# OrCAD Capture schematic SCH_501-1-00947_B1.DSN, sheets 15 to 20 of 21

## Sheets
15 P12_WiFI/BT: size A2
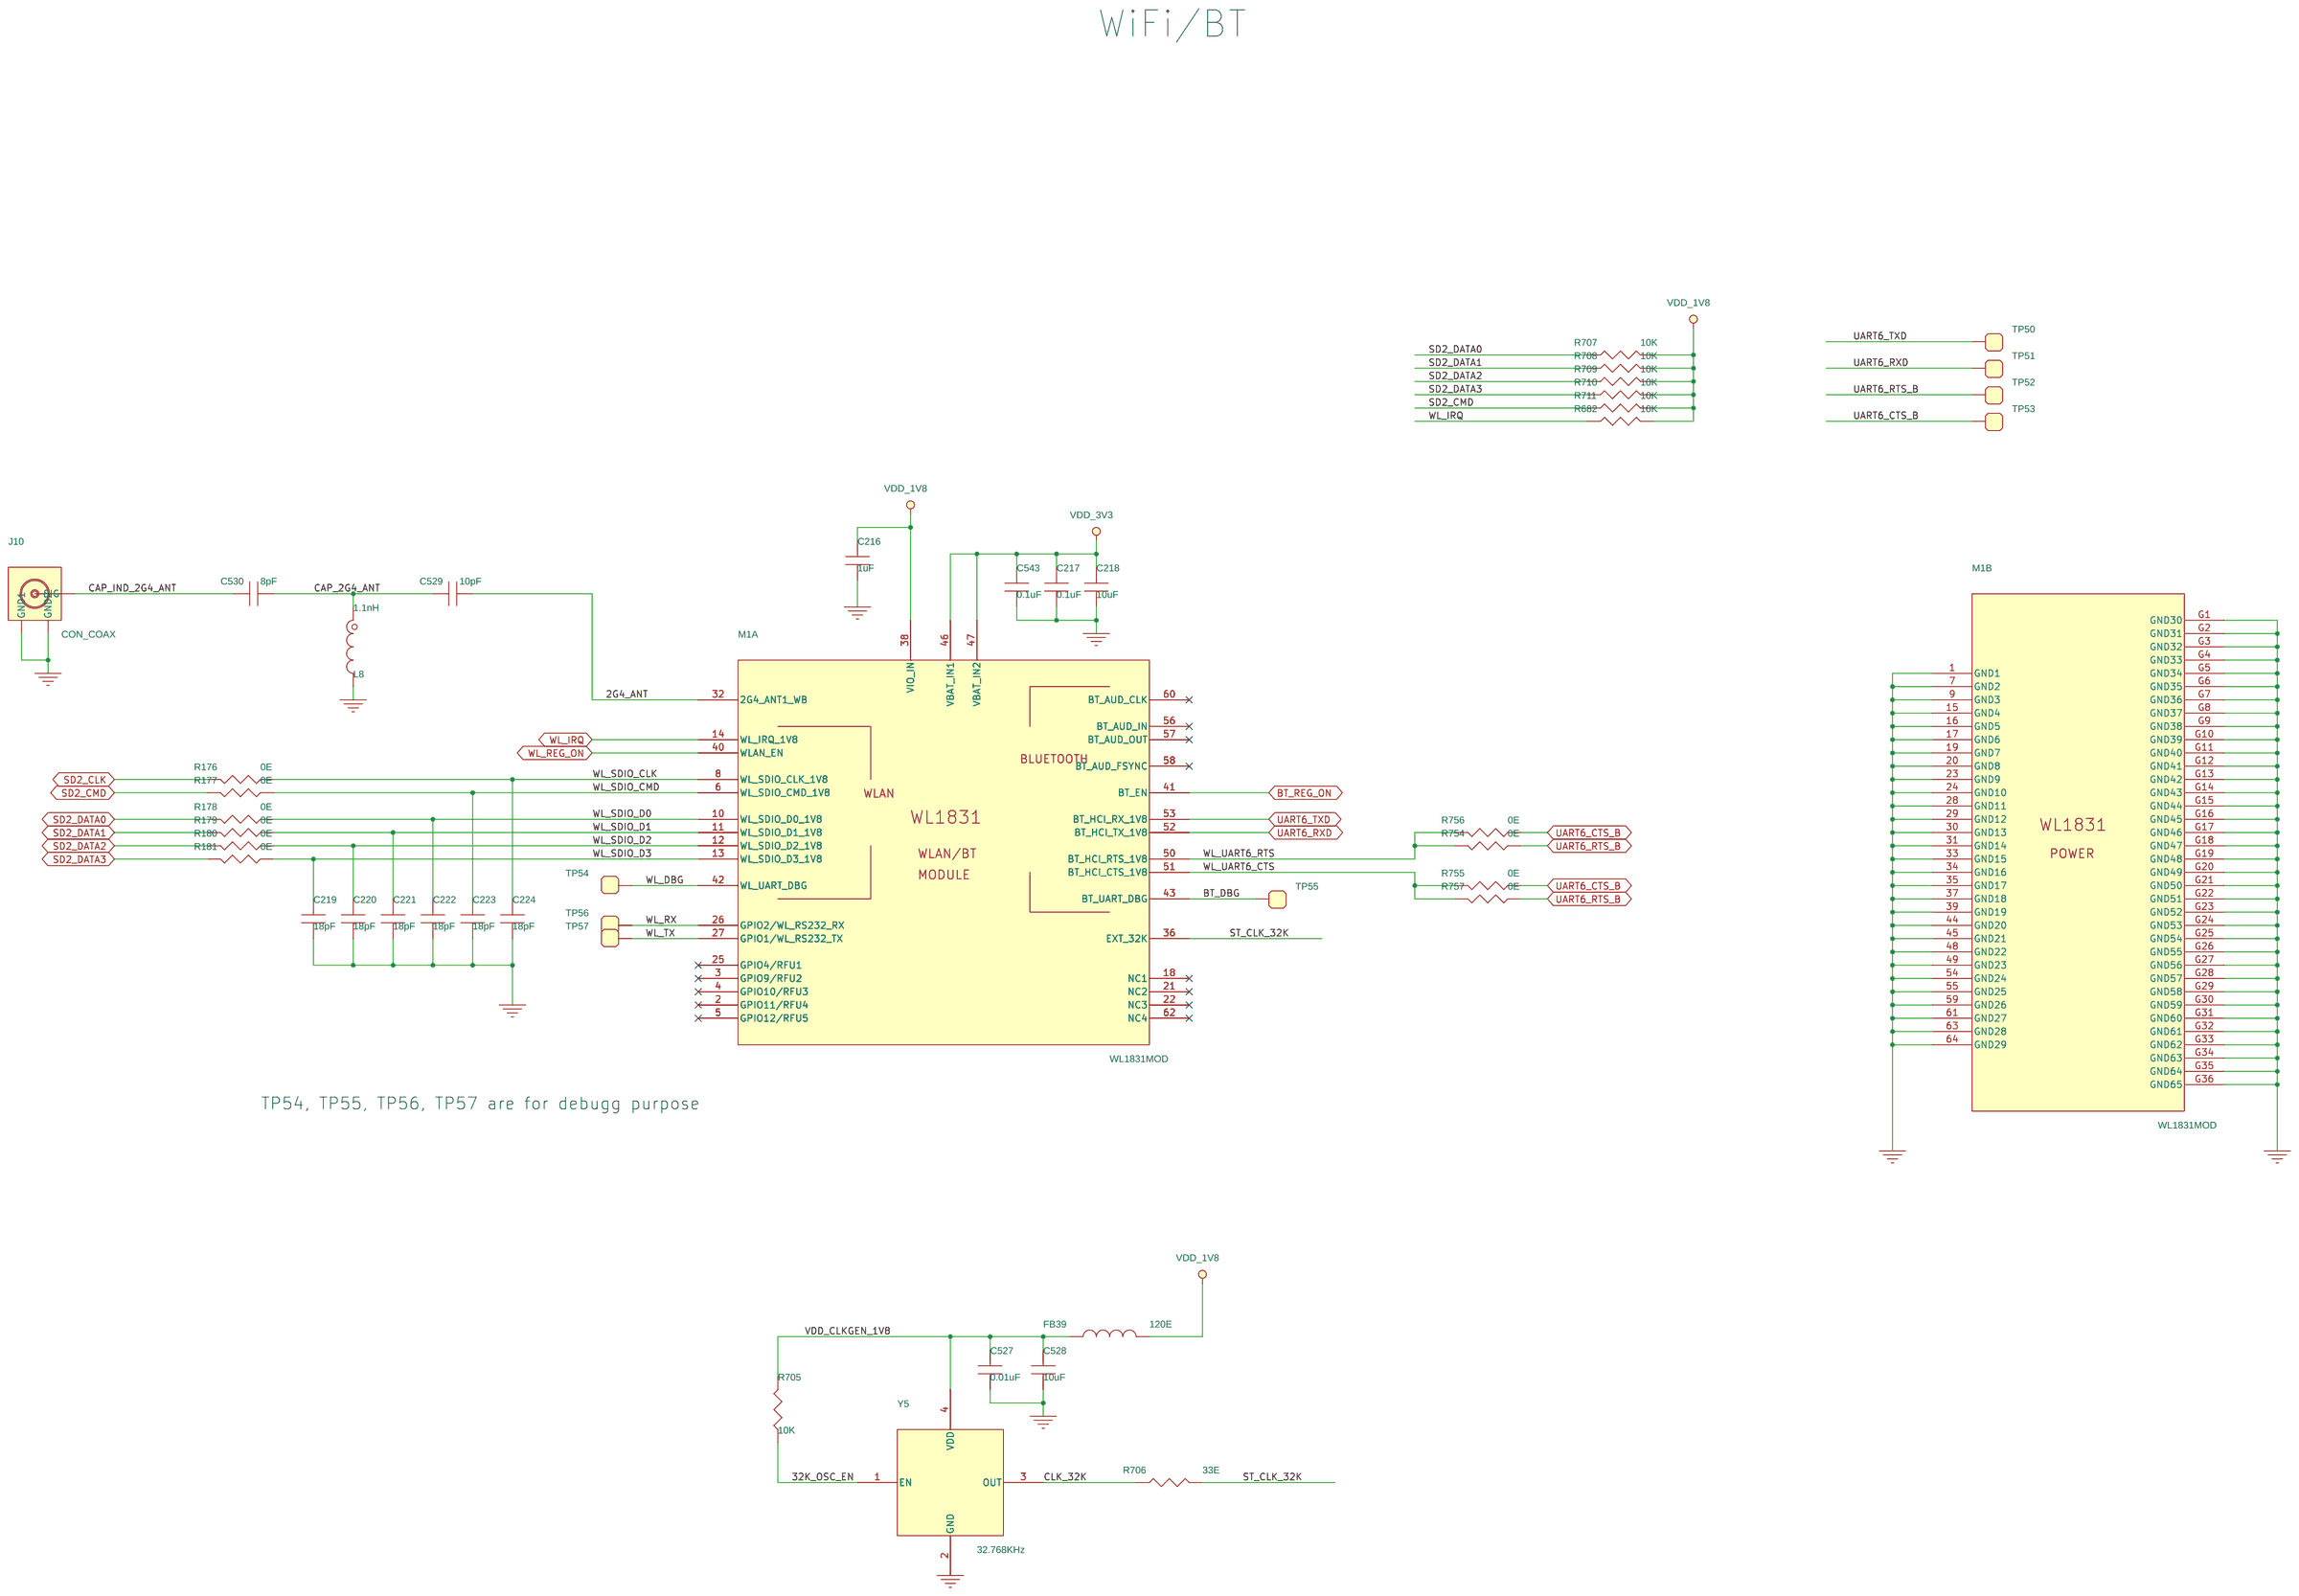
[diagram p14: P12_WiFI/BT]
16 P18_USB/BUTTON: size A2
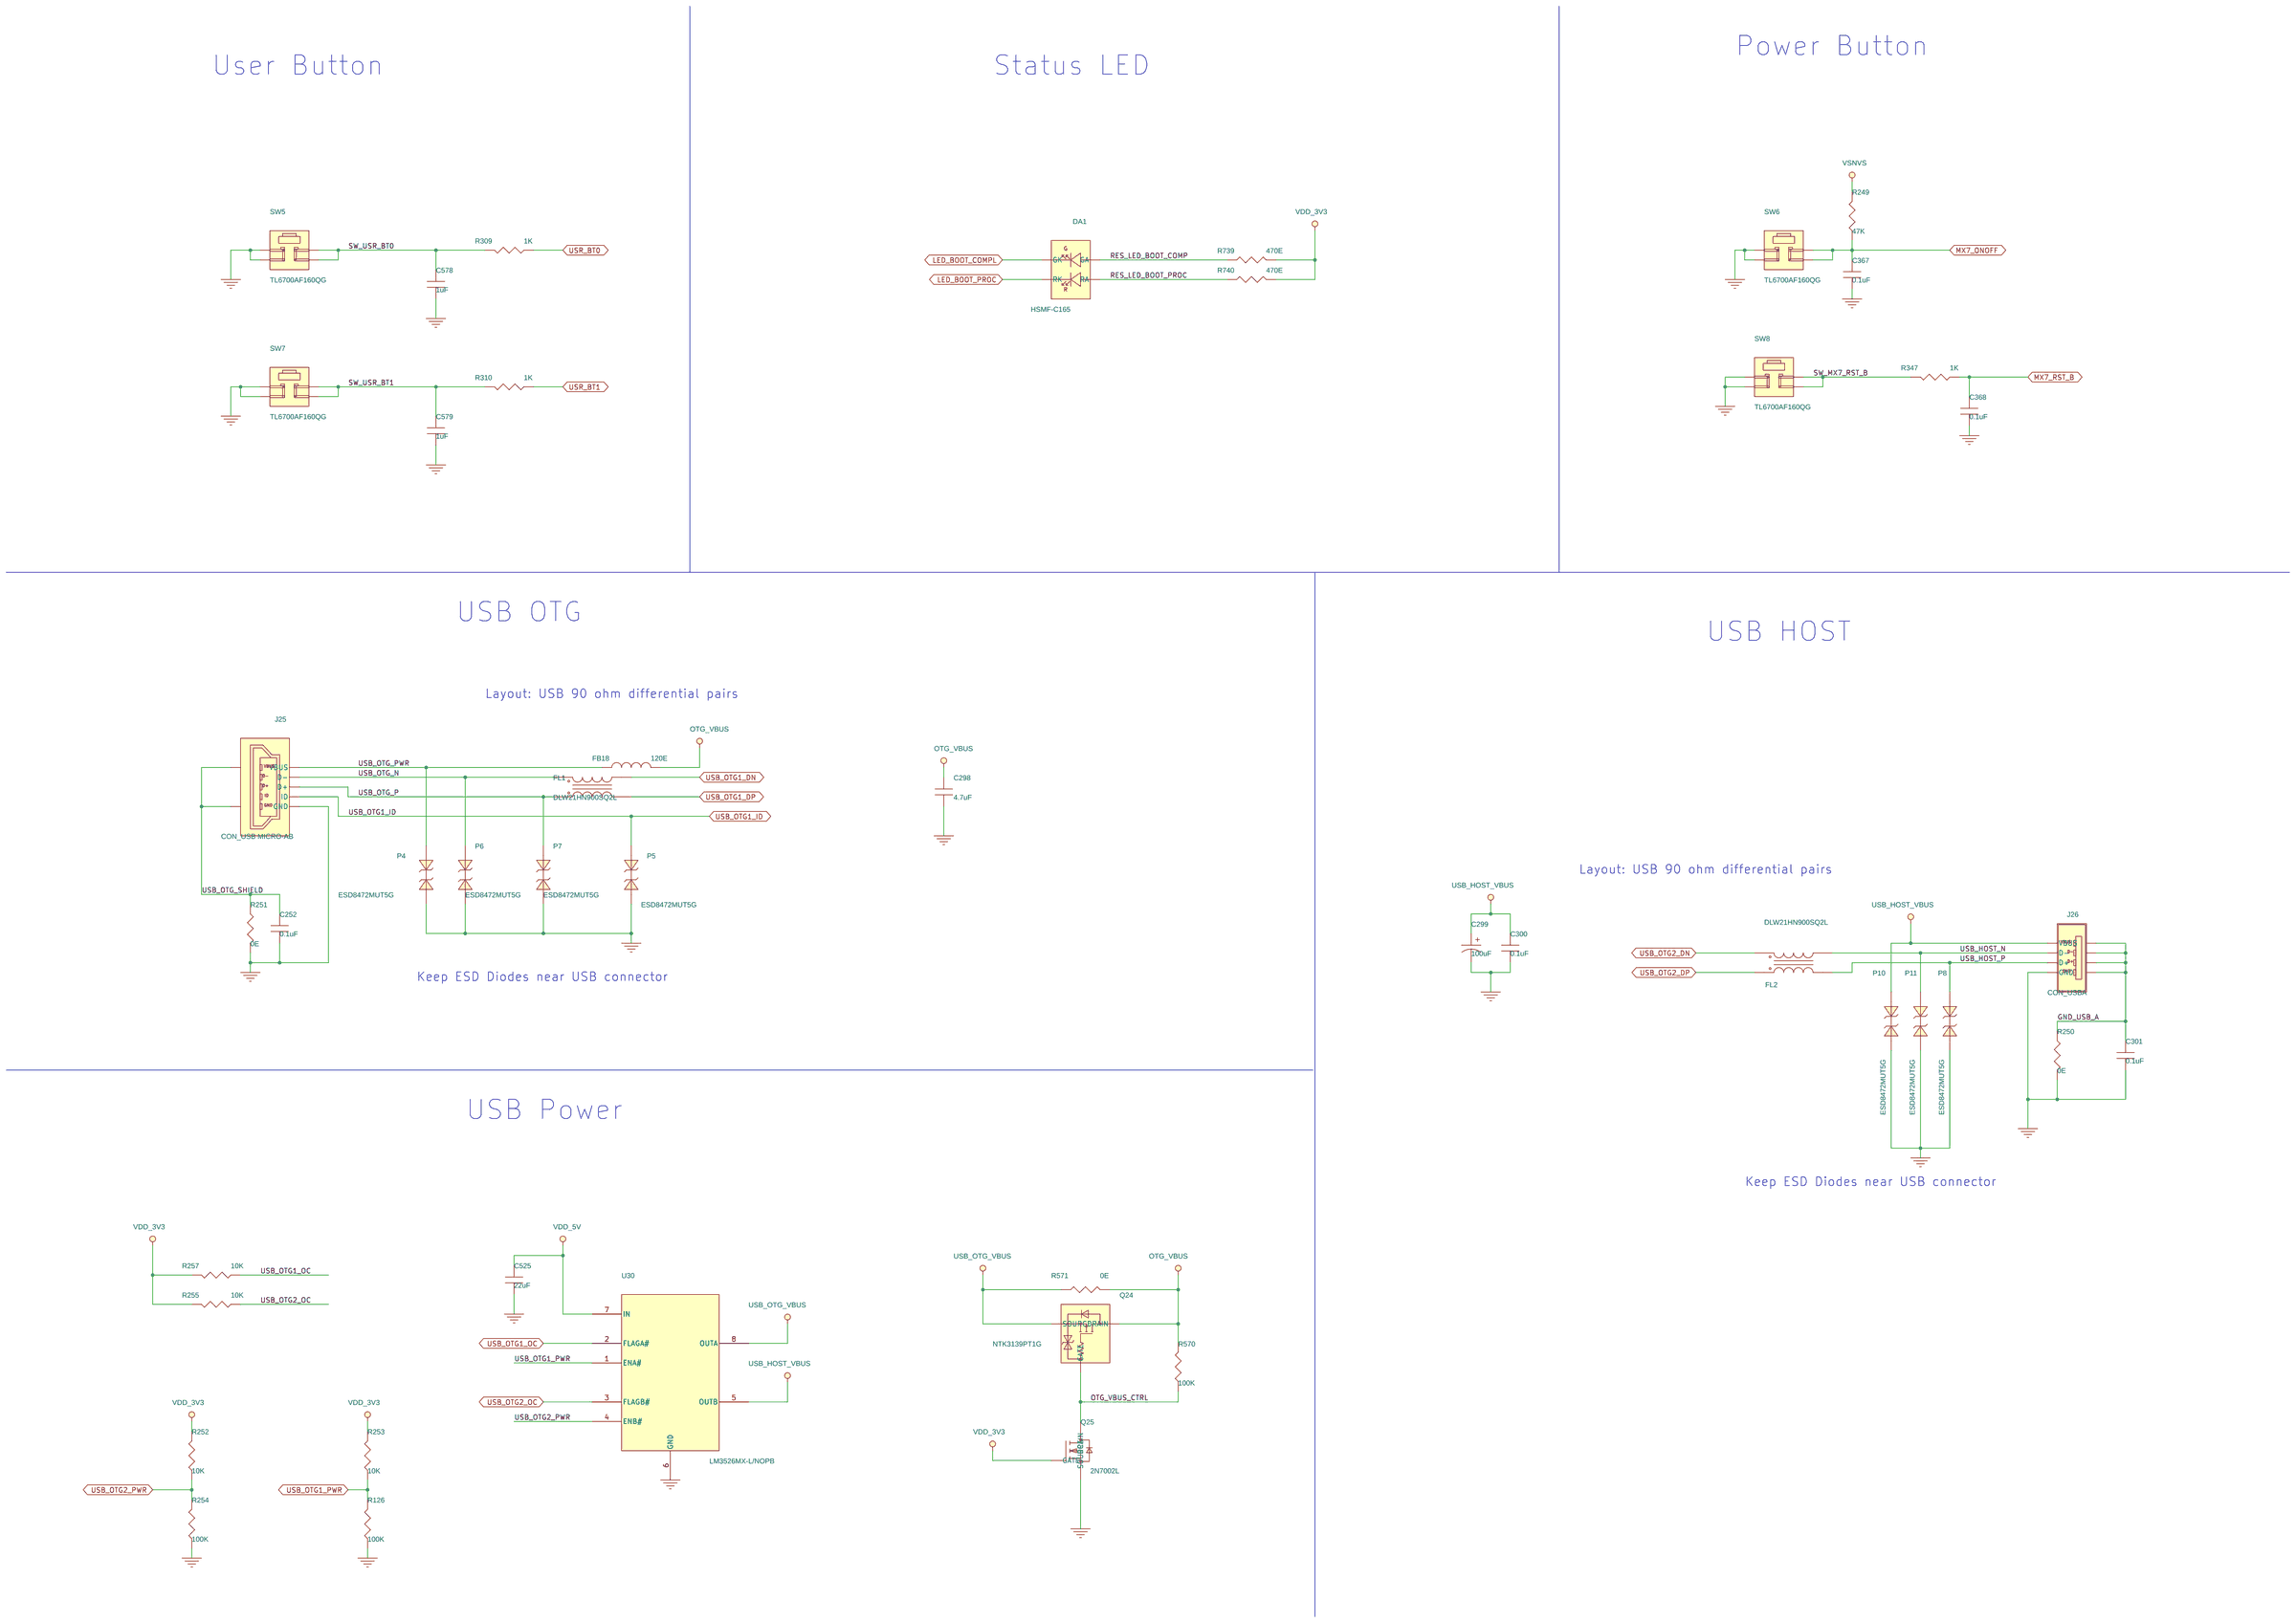
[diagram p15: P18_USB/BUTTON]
17 P16_CAN/LCD/ALS: size A2
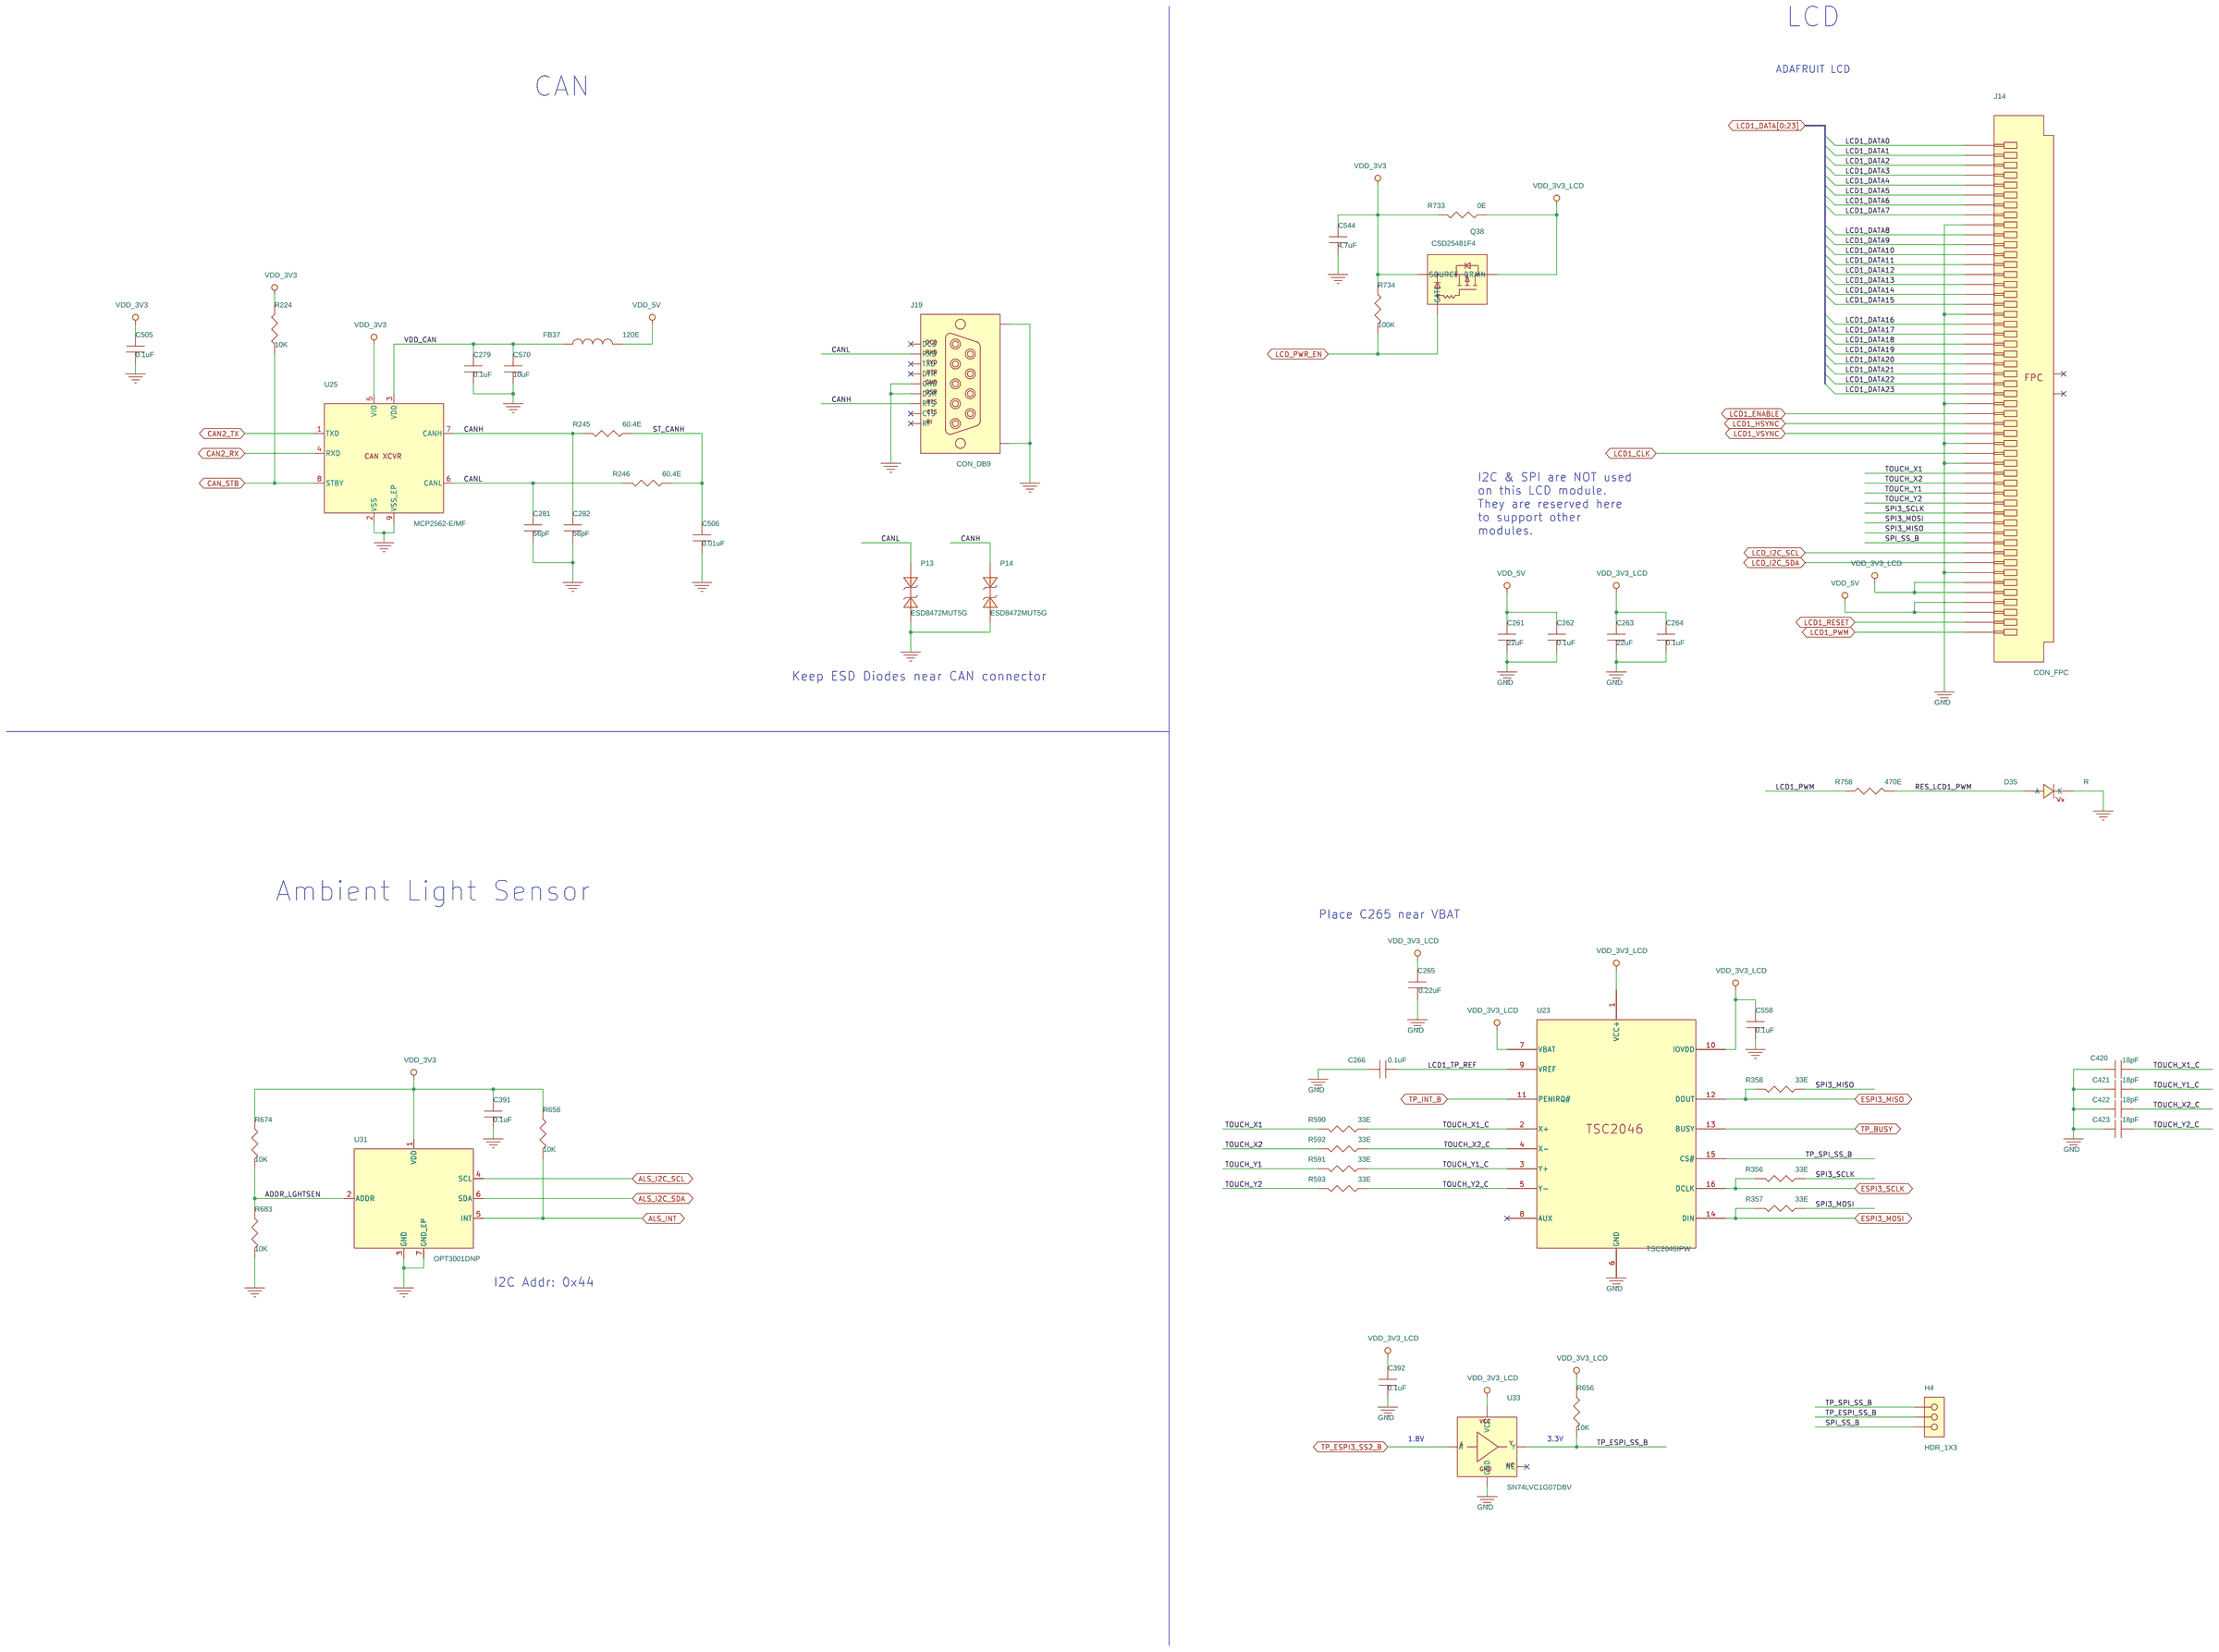
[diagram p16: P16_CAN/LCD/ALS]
18 P10_eMMC/FLASH/SD: size A2
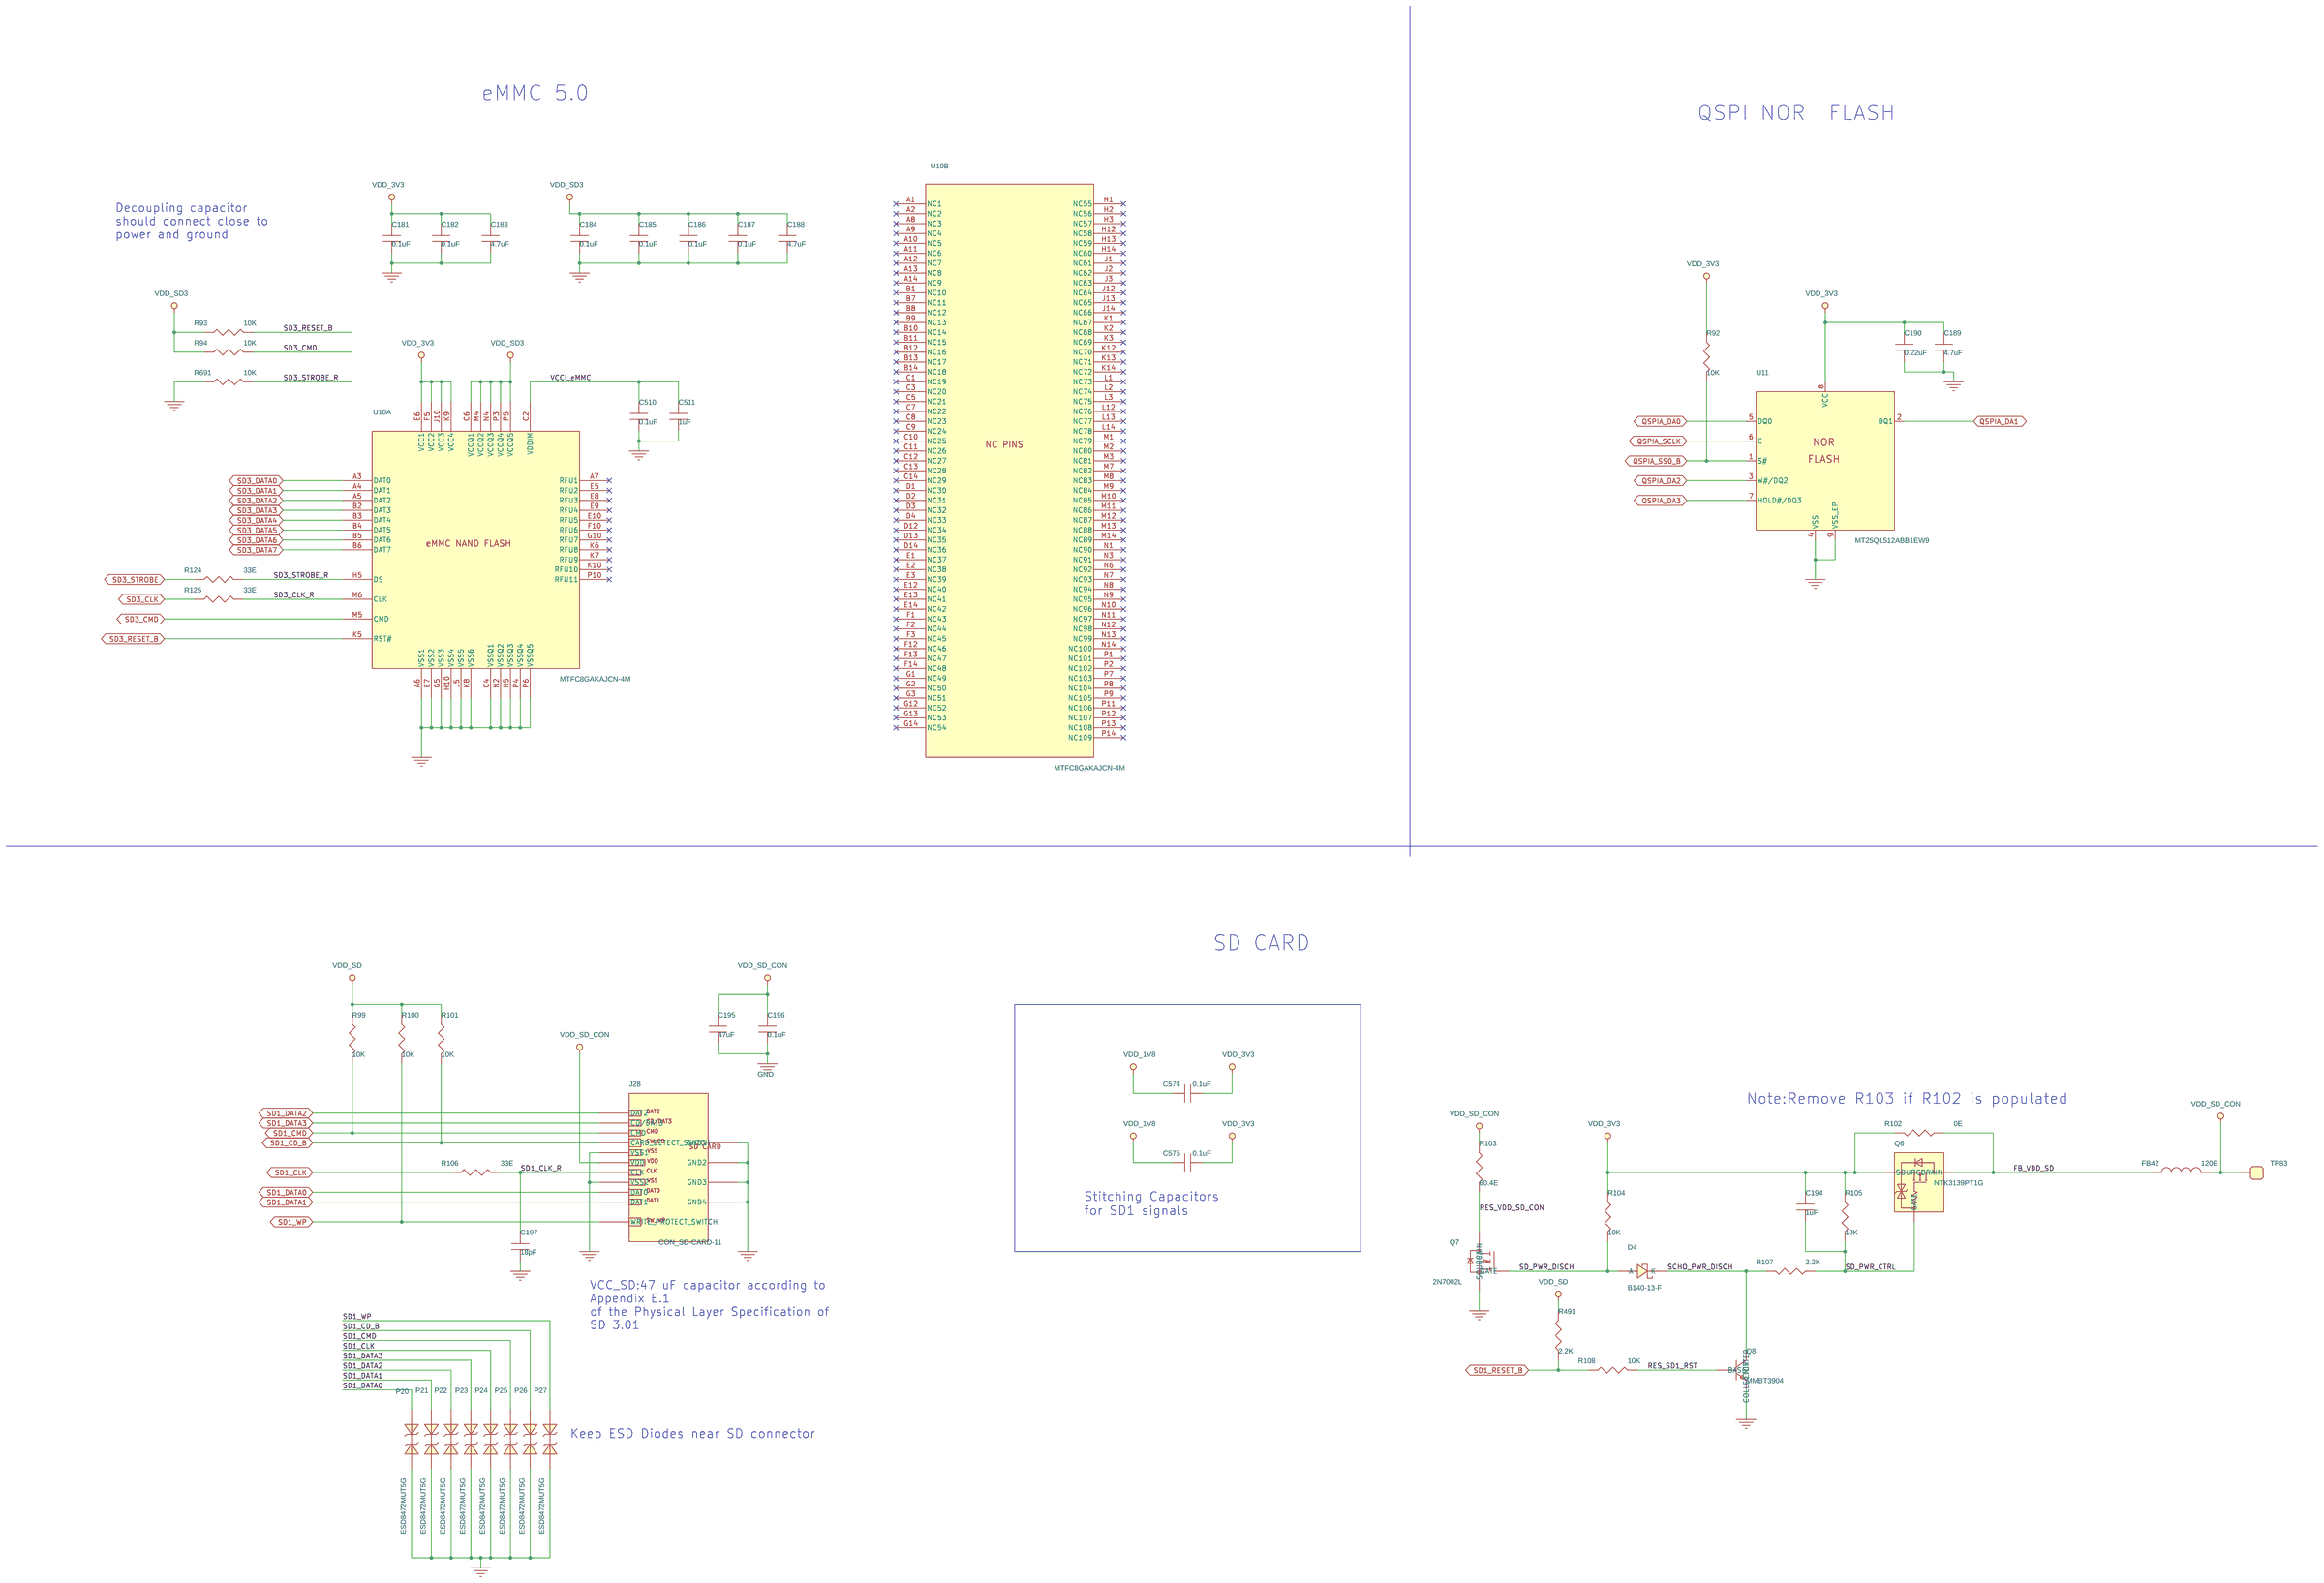
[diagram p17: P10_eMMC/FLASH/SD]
19 P20_CSI/WATCHDOG/IO: size A2
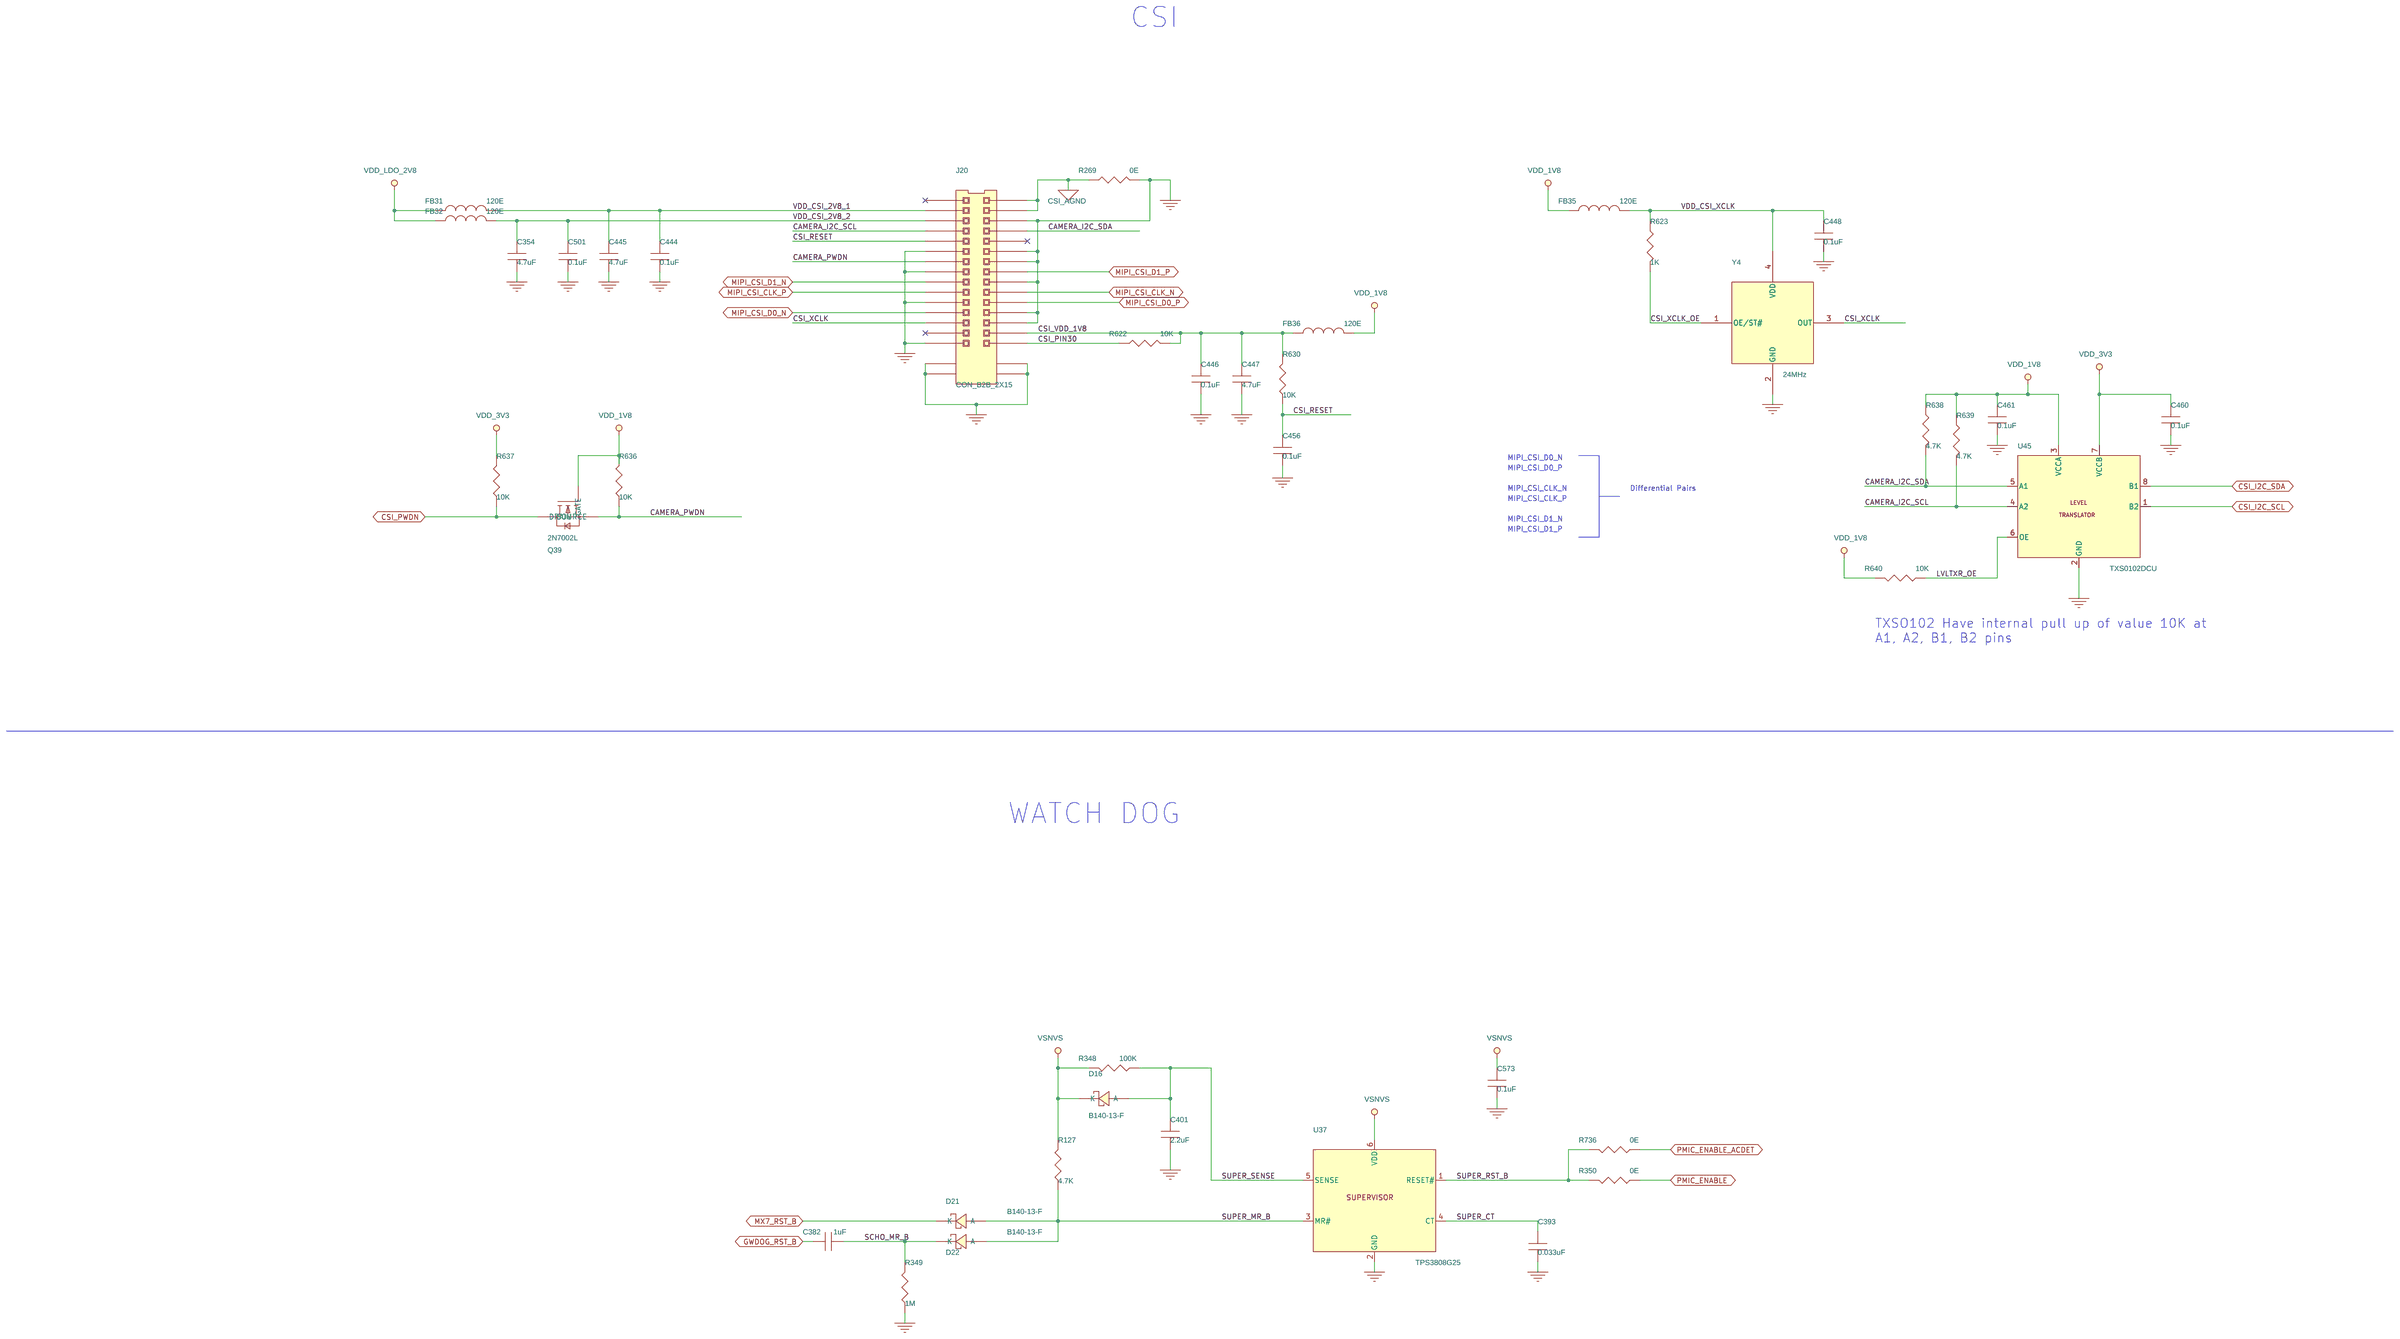
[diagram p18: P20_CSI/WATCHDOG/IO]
20 P13_DEBUG UART/JTAG: size A2
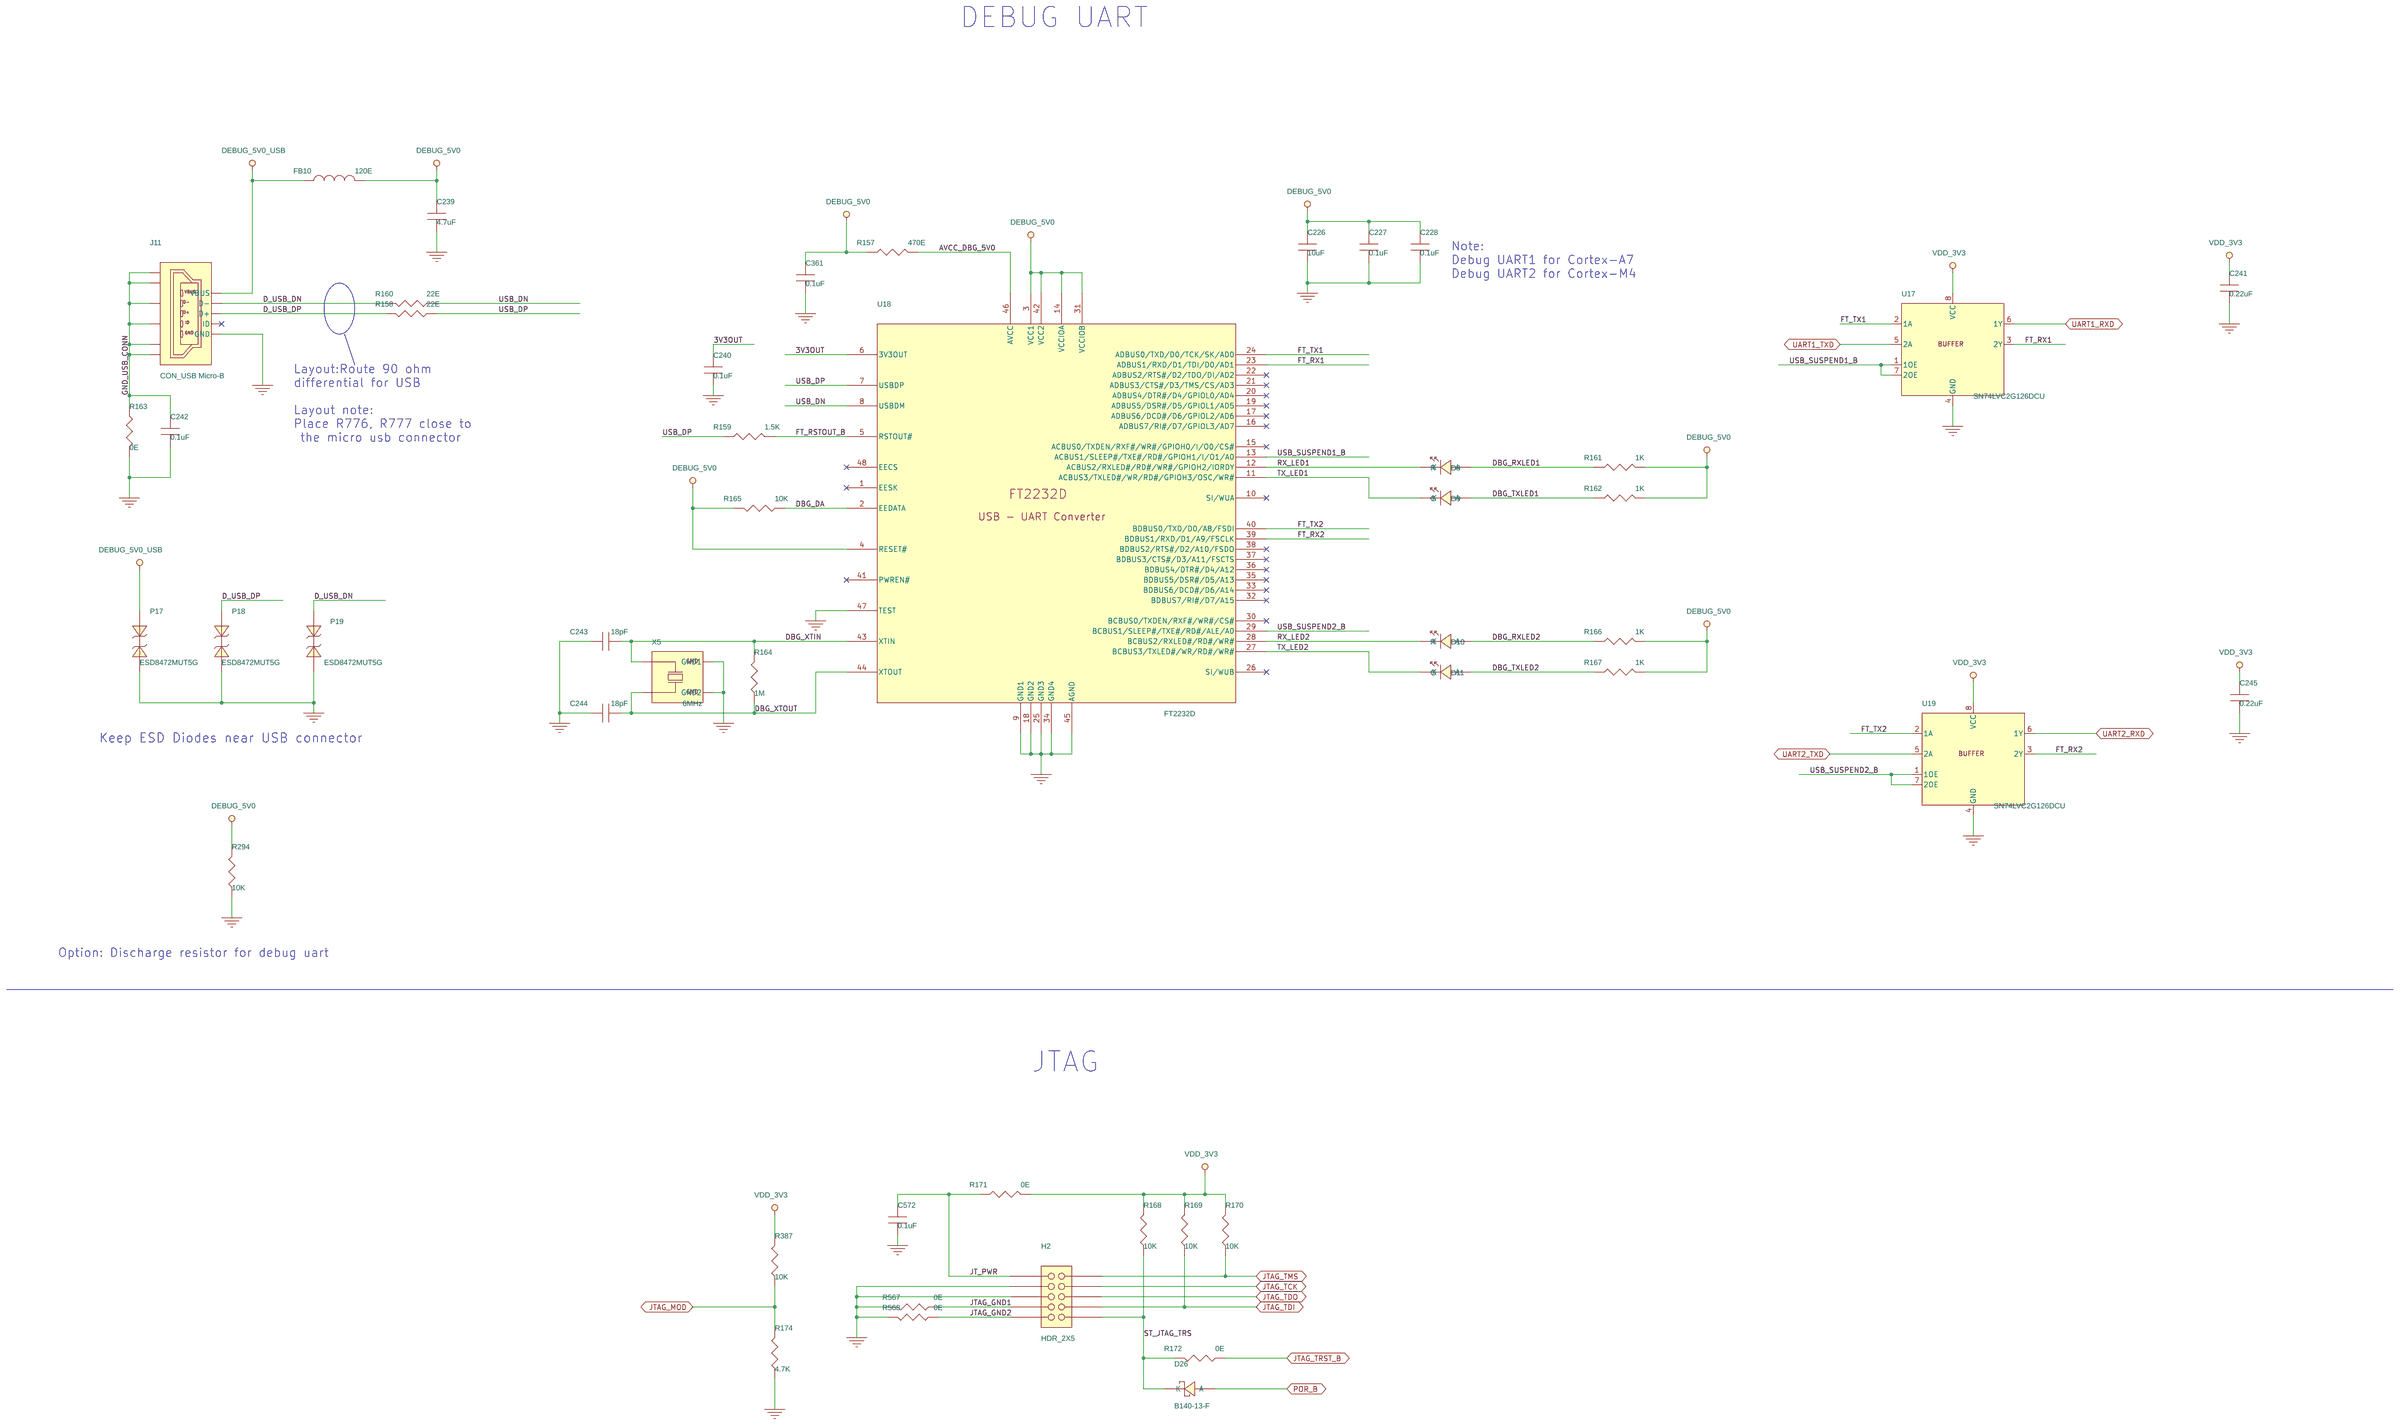
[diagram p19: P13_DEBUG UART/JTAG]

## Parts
sheet P10_eMMC/FLASH/SD
C181  0.1uF  [C0402]
C182  0.1uF  [C0402]
C183  4.7uF  [C0603]
C184  0.1uF  [C0402]
C185  0.1uF  [C0402]
C186  0.1uF  [C0402]
C187  0.1uF  [C0402]
C188  4.7uF  [C0603]
C189  4.7uF  [C0603]
C190  0.22uF  [C0402]
C194  1uF  [C0603]
C195  47uF  [0805_B_A1]
C196  0.1uF  [C0402]
C197  18pF  [C0402]
C510  0.1uF  [C0402]
C511  1uF  [C0603]
C574  0.1uF  [C0402]
C575  0.1uF  [C0402]
D4  B140-13-F  [DIO_SMA]
FB42  120E  [0402]
J28  CON_SD-CARD-11  [CON_SDCARD_11F_2P5_SM_RA_A_A1]
P20  ESD8472MUT5G  [DIO-0201]
P21  ESD8472MUT5G  [DIO-0201]
P22  ESD8472MUT5G  [DIO-0201]
P23  ESD8472MUT5G  [DIO-0201]
P24  ESD8472MUT5G  [DIO-0201]
P25  ESD8472MUT5G  [DIO-0201]
P26  ESD8472MUT5G  [DIO-0201]
P27  ESD8472MUT5G  [DIO-0201]
Q6  NTK3139PT1G  [SOT723-3L_0P4_1P2X0P8]
Q7  2N7002L  [sot23_123]
Q8  MMBT3904  [sot23_123]
R92  10K  [R0402]
R93  10K  [R0402]
R94  10K  [R0402]
R99  10K  [R0402]
R100  10K  [R0402]
R101  10K  [R0402]
R102  0E  [R0402]
R103  60.4E  [R0805]
R104  10K  [R0402]
R105  10K  [R0402]
R106  33E  [R0402]
R107  2.2K  [R0402]
R108  10K  [R0402]
R124  33E  [R0402]
R125  33E  [R0402]
R491  2.2K  [R0402]
R691  10K  [R0402]
TP83  SMD  [TP40_SMD]
U10  MTFC8GAKAJCN-4M  [BGA153_0P5_11P5X13_C_A1]  (sections A,B)
U11  MT25QL512ABB1EW9  [DFN8_1P27_8X6_EP_A_A1]
sheet P12_WiFI/BT
C216  1uF  [C0603]
C217  0.1uF  [C0402]
C218  10uF  [C0603]
C219  18pF  [C0402]
C220  18pF  [C0402]
C221  18pF  [C0402]
C222  18pF  [C0402]
C223  18pF  [C0402]
C224  18pF  [C0402]
C527  0.01uF  [C0402]
C528  10uF  [C0603]
C529  10pF  [0402]
C530  8pF  [0402]
C543  0.1uF  [C0402]
FB39  120E  [0402]
J10  CON_COAX  [CON_COAXIAL_3F_1P475_SM_ST]
L8  1.1nH  [IND_0402-POL]
M1  WL1831MOD  [MOD-WIFI-BT64_0P7_13P4X13P3]  (sections A,B)
R176  0E  [R0402]
R177  0E  [R0402]
R178  0E  [R0402]
R179  0E  [R0402]
R180  0E  [R0402]
R181  0E  [R0402]
R682  10K  [R0402]
R705  10K  [R0402]
R706  33E  [R0402]
R707  10K  [R0402]
R708  10K  [R0402]
R709  10K  [R0402]
R710  10K  [R0402]
R711  10K  [R0402]
R754  0E  [R0402]
R755  0E  [R0402]
R756  0E  [R0402]
R757  0E  [R0402]
TP50  SMD  [TP40_SMD]
TP51  SMD  [TP40_SMD]
TP52  SMD  [TP40_SMD]
TP53  SMD  [TP40_SMD]
TP54  SMD  [TP40_SMD]
TP55  SMD  [TP40_SMD]
TP56  SMD  [TP40_SMD]
TP57  SMD  [TP40_SMD]
Y5  32.768KHz  [OSC4_3P2X2P5_SMD]
sheet P13_DEBUG UART/JTAG
C226  10uF  [C0603]
C227  0.1uF  [C0402]
C228  0.1uF  [C0402]
C239  4.7uF  [C0603]
C240  0.1uF  [C0402]
C241  0.22uF  [C0402]
C242  0.1uF  [C0402]
C243  18pF  [C0402]
C244  18pF  [C0402]
C245  0.22uF  [C0402]
C361  0.1uF  [C0402]
C572  0.1uF  [C0402]
D8  R  [LED2_1P5_1P6X0P8_A_A1]
D9  G  [LED2_1P5_1P6X0P8_A_A1]
D10  R  [LED2_1P5_1P6X0P8_A_A1]
D11  G  [LED2_1P5_1P6X0P8_A_A1]
D26  B140-13-F  [DIO_SMA]
FB10  120E  [0402]
H2  HDR_2X5  [CON_B2B_2X5M_1P27_SM_ST]
J11  CON_USB Micro-B  [CON_USB_1X1-5F_0P65_SM_RA_D_A1]
P17  ESD8472MUT5G  [DIO-0201]
P18  ESD8472MUT5G  [DIO-0201]
P19  ESD8472MUT5G  [DIO-0201]
R157  470E  [R0402]
R158  22E  [R0402]
R159  1.5K  [R0402]
R160  22E  [R0402]
R161  1K  [R0402]
R162  1K  [R0402]
R163  0E  [R0402]
R164  1M  [R0402]
R165  10K  [R0402]
R166  1K  [R0402]
R167  1K  [R0402]
R168  10K  [R0402]
R169  10K  [R0402]
R170  10K  [R0402]
R171  0E  [R0402]
R172  0E  [R0402]
R174  4.7K  [R0402]
R294  10K  [R0402]
R387  10K  [R0402]
R567  0E  [R0402]
R568  0E  [R0402]
U17  SN74LVC2G126DCU  [dcu8p5r]
U18  FT2232D  [QFP48p5j]
U19  SN74LVC2G126DCU  [dcu8p5r]
X5  6MHz  [XTAL4_2P54_7X5_A_A1]
sheet P16_CAN/LCD/ALS
C261  22uF  [C0603]
C262  0.1uF  [C0402]
C263  22uF  [C0603]
C264  0.1uF  [C0402]
C265  0.22uF  [C0402]
C266  0.1uF  [C0402]
C279  0.1uF  [C0402]
C281  56pF  [C0402]
C282  56pF  [C0402]
C391  0.1uF  [C0402]
C392  0.1uF  [C0402]
C420  18pF  [C0402]
C421  18pF  [C0402]
C422  18pF  [C0402]
C423  18pF  [C0402]
C505  0.1uF  [C0402]
C506  0.01uF  [C0402]
C544  4.7uF  [C0603]
C558  0.1uF  [C0402]
C570  10uF  [C0603]
D35  R  [LED2_1P5_1P6X0P8_A_A1]
FB37  120E  [0402]
H4  HDR_1X3  [CON_BERG_3M_2P54_TH_54101]
J14  CON_FPC  [CON_FPC_50F_0P5_SM_RA]
J19  CON_DB9  [CON_DB_9M_2P74_5747840-4]
P13  ESD8472MUT5G  [DIO-0201]
P14  ESD8472MUT5G  [DIO-0201]
Q38  CSD25481F4  [MOSFET_0402-3L_A1]
R224  10K  [R0402]
R245  60.4E  [R0805]
R246  60.4E  [R0805]
R356  33E  [R0402]
R357  33E  [R0402]
R358  33E  [R0402]
R590  33E  [R0402]
R591  33E  [R0402]
R592  33E  [R0402]
R593  33E  [R0402]
R656  10K  [R0402]
R658  10K  [R0402]
R674  10K  [R0402]
R683  10K  [R0402]
R733  0E  [R0402]
R734  100K  [R0402]
R758  470E  [R0402]
U23  TSC2046IPW  [tssop16fa]
U25  MCP2562-E/MF  [DFN8_0P65_3X3_EP_A]
U31  OPT3001DNP  [SON6_0P65_2X2_EP_A_A1]
U33  SN74LVC1G07DBV  [SOT23-5L_0P95_3P05X1P75]
sheet P18_USB/BUTTON
C252  0.1uF  [C0402]
C298  4.7uF  [C0603]
C299  100uF  [TCAP_CASEB]
C300  0.1uF  [C0402]
C301  0.1uF  [C0402]
C367  0.1uF  [C0402]
C368  0.1uF  [C0402]
C525  22uF  [C0603]
C578  1uF  [0402]
C579  1uF  [0402]
DA1  HSMF-C165  [LED4_0P7_1P6X0P8]
FB18  120E  [0402]
FL1  DLW21HN900SQ2L  [CM_CHK4_0P8_2X1P2]
FL2  DLW21HN900SQ2L  [CM_CHK4_0P8_2X1P2]
J25  CON_USB MICRO-AB  [CON_USB_5F_0P65_SM_RA]
J26  CON_USBA  [CON_USB-A_1X1F_2_TH_RA_D_A1]
P4  ESD8472MUT5G  [DIO-0201]
P5  ESD8472MUT5G  [DIO-0201]
P6  ESD8472MUT5G  [DIO-0201]
P7  ESD8472MUT5G  [DIO-0201]
P8  ESD8472MUT5G  [DIO-0201]
P10  ESD8472MUT5G  [DIO-0201]
P11  ESD8472MUT5G  [DIO-0201]
Q24  NTK3139PT1G  [SOT723-3L_0P4_1P2X0P8]
Q25  2N7002L  [sot23_123]
R126  100K  [R0402]
R249  47K  [R0402]
R250  0E  [R0402]
R251  0E  [R0402]
R252  10K  [R0402]
R253  10K  [R0402]
R254  100K  [R0402]
R255  10K  [R0402]
R257  10K  [R0402]
R309  1K  [R0402]
R310  1K  [R0402]
R347  1K  [R0402]
R570  100K  [R0402]
R571  0E  [R0402]
R739  470E  [R0402]
R740  470E  [R0402]
SW5  TL6700AF160QG  [SW4_4_6P9X6P2]
SW6  TL6700AF160QG  [SW4_4_6P9X6P2]
SW7  TL6700AF160QG  [SW4_4_6P9X6P2]
SW8  TL6700AF160QG  [SW4_4_6P9X6P2]
U30  LM3526MX-L/NOPB  [SOIC8_1P27_4X5]
sheet P20_CSI/WATCHDOG/IO
C354  4.7uF  [C0603]
C382  1uF  [C0603]
C393  0.033uF  [C0402]
C401  2.2uF  [C0402]
C444  0.1uF  [C0402]
C445  4.7uF  [C0603]
C446  0.1uF  [C0402]
C447  4.7uF  [C0603]
C448  0.1uF  [C0402]
C456  0.1uF  [C0402]
C460  0.1uF  [C0402]
C461  0.1uF  [C0402]
C501  0.1uF  [C0402]
C573  0.1uF  [C0402]
D16  B140-13-F  [DIO_SMA]
D21  B140-13-F  [DIO_SMA]
D22  B140-13-F  [DIO_SMA]
FB31  120E  [0402]
FB32  120E  [0402]
FB35  120E  [0402]
FB36  120E  [0402]
J20  CON_B2B_2X15  [fpc2x15_4p4_a]
Q39  2N7002L  [sot23_123]
R127  4.7K  [R0402]
R269  0E  [R0402]
R348  100K  [R0402]
R349  1M  [R0402]
R350  0E  [R0402]
R622  10K  [R0402]
R623  1K  [R0402]
R630  10K  [R0402]
R636  10K  [R0402]
R637  10K  [R0402]
R638  4.7K  [R0402]
R639  4.7K  [R0402]
R640  10K  [R0402]
R736  0E  [R0402]
U37  TPS3808G25  [SOT23-6L_0P95_3P05X1P75]
U45  TXS0102DCU  [ssop8cr]
Y4  24MHz  [OSC4_1P9_3P2X2P5_C_A1]

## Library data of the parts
C181 C182 C184-C187 C196 C217 C227 C228 C240 C279 C391 C392 C505 C510 C543 C558 C572-C575 = CAP_NP: Cap, Cer-X7R, 0.1uF, 16V, 10%, 0402; EN: 102-1-01629; KEY Number: 102-1-01629@4; Mfg: MURATA MANUFACTURING CO,LTD; Mfg Part No: GRM155R71C104KA88*; Temperature: -55°C to +125°C
C183 C188 C189 C354 C445 C447 = CAP_NP: Cap, Cer-X5R, 4.7uF, 10V, 10%, 0603; EN: 102-1-01650; KEY Number: 102-1-01650@2; Mfg: WALSIN TECHNOLOGY CORP.; Mfg Part No: 0603X475K100CT; Temperature: -55°C to +85°C
C190 C241 C245 C265 = CAP_NP: Cap, Cer-X5R, 0.22uF, 10V, 10%, 0402; EN: 102-1-00210; FPLIST: 0402,0402_CIR_A1; KEY Number: 102-1-00210@1; Mfg: MURATA MANUFACTURING CO,LTD; Mfg Part No: GRM155R61A224KE19D; Temperature: -55°C to +85°C
C194 C216 C382 C511 = CAP_NP: Cap, Cer-X7R, 1uF, 10V, 10%, 0603; EN: 102-1-00097; FPLIST: 0603,0603_HD; KEY Number: 102-1-00097@1; Mfg: AVX CORPORATION; Mfg Part No: 0603ZC105KAT2A; Temperature: -55°C to +125°C
C195 = CAP_NP: Cap, Cer-X5R, 47uF, 10V, 20%, 0805; EN: 102-1-02136; KEY Number: 102-1-02136@1; Mfg: MURATA MANUFACTURING CO,LTD; Mfg Part No: GRM21BR61A476ME15L; Temperature: -55°C to +85°C
C197 C219-C224 C243 C244 C420-C423 = CAP_NP: Cap, Cer-NPO, 18pF, 50V, 5%, 0402; EN: 102-1-01806; KEY Number: 102-1-01806@1; Mfg: MURATA MANUFACTURING CO,LTD; Mfg Part No: GRM1555C1H180JA01D; Temperature: -55°C to +125°C
D4 D16 D21 D22 D26 = DIODE_SCH: Diode, Schottky, 1A, 40V, SMA; EN: 106-2-00036; KEY Number: 106-2-00036@1; Mfg: DIODES INCORPORATED
FB10 FB18 FB31 FB32 FB35-FB37 FB39 FB42 = FER_BEAD: F-Bead, 120E, 1.3A, SMD0402; EN: 104-1-00007; KEY Number: 104-1-00007@1; Mfg: MURATA MANUFACTURING CO,LTD; Mfg Part No: BLM15PD121SN1B; Temperature: -55°C to +125°C
J28 = CONN_SD-CARD-11_14P_A1: Conn, SD card Socket, 1x1, Shield, Push-Pull, RA, SMD; EN: 201-2-00848; KEY Number: 201-2-00848@1; Mfg: WURTH ELECTRONIK, INC; Mfg Part No: 693063020911; Temperature: -25°C to +85°C
P4-P8 P10 P11 P13 P14 P17-P27 = PROT_ZENX2_NET_2P_A: TVS-Zener Diode, Bi, 7V, X3DFN2; EN: 305-1-00135; KEY Number: 305-1-00135@1; Mfg: ON SEMICONDUCTOR; Temperature: -55°C to +150°C
Q6 Q24 = TRANS_PMOS-ENX1_3P_E: Transistor, P-MOSFET, 20V, 0.78A, Vgs=6V, 0.45W, SOT-723-3; EN: 107-2-00139; KEY Number: 107-2-00139@1; Mfg: ON SEMICONDUCTOR; Temperature: -55°C to +150°C
Q7 Q25 Q39 = TRANS_NMOS-ENX1_3P: Transistor, N-MOSFET, 60V, 0.115A, Vgs=20V, 0.225W, SOT-23; EN: 107-2-00143; KEY Number: 107-2-00143@1; Mfg: ON SEMICONDUCTOR; Mfg Part No: 2N7002L**G; Temperature: -55°C to +150°C
Q8 = TRANS_NPN: Transistor, BJT, NPN, 40V, 0.2A, SOT23-3; EN: 107-1-00001; KEY Number: 107-1-00001@1; Mfg: FAIRCHILD SEMICONDUCTOR; Temperature: -55°C to +150°C
R92-R94 R99-R101 R104 R105 R108 R165 R168-R170 R224 R252 R253 R255 R257 R294 R387 R622 R630 R636 R637 R640 R656 R658 R674 R682 R683 R691 R705 R707-R711 = RES: Res, Chip, 10K, 1/16W, 5%, 0402; EN: 101-1-02793; KEY Number: 101-1-02793@2; Mfg: VISHAY; Mfg Part No: CRCW040210K0JNED; Temperature: -55°C to +155°C
R102 R163 R171 R172 R176-R181 R250 R251 R269 R350 R567 R568 R571 R733 R736 R754-R757 = RES: Res, Chip, 0E, 1/16W, 1.5A, AEC-Q200, 0402; EN: 101-1-00001; KEY Number: 101-1-00001@2; Mfg: VISHAY; Mfg Part No: CRCW04020000Z0ED; Temperature: -55°C to +155°C
R103 R245 R246 = RES: Res, Chip, 60.4E, 1/8W, 1%, 0805; EN: 101-1-01522; KEY Number: 101-1-01522@2; Mfg: VISHAY; Mfg Part No: CRCW080560R4FK; Temperature: -55°C to +155°C
R106 R124 R125 R356-R358 R590-R593 R706 = RES: Res, Chip, 33E, 1/16W, 1%, 0402; EN: 101-1-03680; KEY Number: 101-1-03680@2; Mfg: WALSIN TECHNOLOGY CORP.; Mfg Part No: WR04X33R0FTL; Temperature: -55°C to +155°C
R107 R491 = RES: Res, Chip, 2.2K, 1/16W, 5%, 0402; EN: 101-1-02777; KEY Number: 101-1-02777@2; Mfg: VISHAY; Mfg Part No: CRCW04022K20JN**; Temperature: -55°C to +155°C
TP50-TP57 TP83 = TEST_POINT_SMD: Testpoint, Pad=1mm, SM=1.3mm, SMD; EN: 666-1-00008; KEY Number: 666-1-00008@1; Mfg: NA; Mfg Part No: 666-1-00008
U10 = IC_NAND_FLASHx8_BGA-153P_J_A1: IC, eMMC 5.0, 8GB, x8bit, 52MHz, VFBGA-153; EN: 301-2-00608; KEY Number: 301-2-00608@1; Mfg: MICRON; Mfg Part No: MTFC8GAKAJCN-4M IT; Temperature: -40°C to +85°C
U11 = IC_NORFLASH-SPI_8P_EP_G_A1: IC, NOR Flash, 64MB, SPI, 133MHz, 2.7-3.6V, W-PDFN-8; EN: 301-2-00441; KEY Number: 301-2-00441@1; Mfg: MICRON; Mfg Part No: MT25QL512ABB1EW9-0SIT; Temperature: -40°C to +85°C
C218 C226 C528 C570 = CAP_NP: Cap, Cer-X5R, 10uF, 10V, 10%, 0603; EN: 102-1-00156; KEY Number: 102-1-00156@2; Mfg: WALSIN TECHNOLOGY CORP.; Mfg Part No: 0603X106K100CT; Temperature: -55°C to +85°C
C506 C527 = CAP_NP: Cap, Cer-X7R, 0.01uF, 10V, 10%, 0402; EN: 102-1-00001; KEY Number: 102-1-00001@1; Mfg: AVX CORPORATION; Mfg Part No: 0402ZC103KAT2A; Temperature: -55°C to +125°C
C529 = CAP_NP: Cap, RF, Cer-NPO, 10pF, 50V, 1%, Low ESR, 0402; EN: 102-4-00002; KEY Number: 102-4-00002@1; Mfg: AVX CORPORATION; Mfg Part No: 04025U100FAT**; Temperature: -55°C to +125°C
C530 = CAP_NP: Cap, RF, Cer-NPO, 8pF, 50V, +/-0.25pF, Low ESR, 0402; EN: 102-4-00015; KEY Number: 102-4-00015@1; Mfg: MURATA MANUFACTURING CO,LTD; Mfg Part No: GJM1555C1H8R0CB01D; Temperature: -55°C to +125°C
J10 = CONN_COAX_3P: Conn, Coaxial, Receptacle, 50E, 6GHz, ST, SMD; EN: 201-1-00107; KEY Number: 201-1-00107@1; Mfg: HRS (HIROSE ELECTRIC CO LTD); Mfg Part No: U.FL-R-SMT-1
L8 = IND_POL: Ind, Chip, 1.1nH, +/-0.3nH, 0.3A, 90mE, Unshielded, 6GHz, SMD0402; EN: 103-1-00193; KEY Number: 103-1-00193@1; Mfg: MURATA MANUFACTURING CO,LTD; Mfg Part No: LQG15HS1N1S02D; Temperature: -55°C to +125°C
M1 = MODRF_WL1831_100P: Module, WiFi+BTv4.0, SDIO+UART, 802.11b/g/n, SMD; EN: 510-4-00017; KEY Number: 510-4-00017@1; Mfg: TEXAS INSTRUMENTS; Temperature: -20°C to +70°C
Y5 = OSC_4P_A: Osc, 32.768KHz, +/-25ppm, 1.8V, CMOS, SMD; EN: 302-1-00008; KEY Number: 302-1-00008@1; Mfg: TXC CORPORATION; Mfg Part No: 7XZ-32.768KDA
C239 C298 C544 = CAP_NP: Cap, Cer-X5R, 4.7uF, 16V, 10%, 0603; EN: 102-1-00091; FPLIST: 0603,0603_HD; KEY Number: 102-1-00091@4; Mfg: MURATA MANUFACTURING CO,LTD; Mfg Part No: GRM188R61C475KAAJ*; Temperature: -55°C to +85°C
C242 C252 C301 = CAP_NP: Cap, Cer-X5R, 0.1uF, 25V, 10%, 0402; EN: 102-1-01693; FPLIST: 0402,0402_CIR_A1; KEY Number: 102-1-01693@1; Mfg: AVX CORPORATION; Mfg Part No: 04023D104KAT2A; Temperature: -55°C to +85°C
C262 C264 C266 C300 C361 C367 C368 C444 C446 C448 C456 C460 C461 C501 = CAP_NP: Cap, Cer-X7R, 0.1uF, 16V, 10%, 0402; EN: 102-1-01629; KEY Number: 102-1-01629@4; Mfg: MURATA MANUFACTURING CO,LTD; Mfg Part No: GRM155R71C104KA88D; Temperature: -55°C to +125°C
D8 D10 D35 = DIODE_LED: LED, Single, RED, SMD; EN: 106-4-00247; KEY Number: 106-4-00247@1; Mfg: LITE-ON; Mfg Part No: LTST-C193KRKT-5A; Temperature: -30°C to +85°C
D9 D11 = DIODE_LED: LED, Single, Green, SMD; EN: 106-4-00248; KEY Number: 106-4-00248@1; Mfg: LITE-ON; Mfg Part No: LTST-C193KGKT-5A; Temperature: -55°C to +85°C
H2 = HDR_2X5_10P: Conn, Berg strip, 2x5, 1.27mm, 1A, ST, SMD; EN: 201-1-00205; KEY Number: 201-1-00205@1; Mfg: FCI; Mfg Part No: 20021121-00010*4LF; Temperature: -55°C to +125°C
J11 = CONN_USB-5X1_11P: Conn, USB Micro-B Receptacle, 1x1, RA, SMD; EN: 201-2-00519; KEY Number: 201-2-00519@1; Mfg: FCI - AMPHENOL ICC; Mfg Part No: 10118193-0001LF; Temperature: -55°C to +85°C
R157 R739 R740 R758 = RES: Res, Chip, 470E, 1/16W, 1%, 100ppm/degC, 0402; EN: 101-1-03571; FPLIST: 0402,0402_HD; KEY Number: 101-1-03571@1; Mfg: VISHAY; Mfg Part No: CRCW0402470RFK; Temperature: -55°C to +155°C
R158 R160 = RES: Res, Chip, 22E, 1/16W, 5%, 0402; EN: 101-1-02729; KEY Number: 101-1-02729@3; Mfg: WALSIN TECHNOLOGY CORP.; Mfg Part No: WR04X220JTL; Temperature: -55°C to +155°C
R159 = RES: Res, Chip, 1.5K, 1/16W, 1%, 0402; EN: 101-1-00310; KEY Number: 101-1-00310@2; Mfg: VISHAY; Mfg Part No: CRCW04021K50FK; Temperature: -55°C to +155°C
R161 R162 R166 R167 R309 R310 R347 R623 = RES: Res, Chip, 1K, 1/16W, 5%, 0402; EN: 101-1-02769; KEY Number: 101-1-02769@4; Mfg: WALSIN TECHNOLOGY CORP.; Mfg Part No: WR04X102JTL; Temperature: -55°C to +155°C
R164 R349 = RES: Res, Chip, 1M, 1/16W, 1%, 0402; EN: 101-1-00581; KEY Number: 101-1-00581@2; Mfg: VISHAY; Mfg Part No: CRCW04021M00FK; Temperature: -55°C to +155°C
R127 R174 R638 R639 = RES: Res, Chip, 4.7K, 1/16W, 1%, 0402; EN: 101-1-03446; KEY Number: 101-1-03446@2; Mfg: WALSIN TECHNOLOGY CORP.; Mfg Part No: WR04X4701FTL; Temperature: -55°C to +155°C
U17 U19 = IC_GATE_BUFX2_8P_B_A1: IC, 74LVC2G126, Dual Bus Buffer, 3 State O/P, VSSOP-8; EN: 301-0-00108; KEY Number: 301-0-00108@1; Mfg: TEXAS INSTRUMENTS; Mfg Part No: SN74LVC2G126DCUR; Temperature: -40°C to +125°C
U18 = IC_FT2232D_LQFP-48P_A1: IC, FT2232D, USB to UART Converter, Dual UART, LQFP-48; EN: 301-0-01483; KEY Number: 301-0-01483@1; Mfg: FTDI CHIP; Temperature: -40°C to +85°C
X5 = CRYSTAL_4P: XTAL, 6MHz, 18pF, +/-20ppm, 70E, 5x7mm, SMD; EN: 108-1-00217; KEY Number: 108-1-00217@1; Mfg: ABRACON CORPORATION; Mfg Part No: ABMM-6.000MHZ-B2-*; Temperature: -10°C to +60°C
C261 C263 C525 = CAP_NP: Cap, Cer-X5R, 22uF, 10V, 20%, 0603; EN: 102-1-01791; KEY Number: 102-1-01791@5; Mfg: MURATA MANUFACTURING CO,LTD; Mfg Part No: GRM188R61A226ME15*; Temperature: -55°C to +85°C
C281 C282 = CAP_NP: Cap, Cer-NPO, 56pF, 50V, 1%, 0402; EN: 102-1-00772; KEY Number: 102-1-00772@3; Mfg: MURATA MANUFACTURING CO,LTD; Mfg Part No: GRM1555C1H560FA01*; Temperature: -55°C to +125°C
H4 = HDR_1X3_3P: Conn, Berg strip, 1x3, 2.54mm, ST, TH; EN: 201-1-00004; KEY Number: 201-1-00004@1; Mfg: FCI; Mfg Part No: 68000-103HLF
J14 = CONN_FPC-50_52P: Conn, FPC, Receptacle, 1x50, 0.5mm, 0.5A, RA, SMD; EN: 201-2-00096; FPLIST: CON_FPC_50F_0P5_SM_RA,CON_FPC_50F_0P5_SM_RA_CUST; KEY Number: 201-2-00096@1; Mfg: HRS (HIROSE ELECTRIC CO LTD); Mfg Part No: FH28D-50S-0.5SH(05)
J19 = CONN_DB9X1_11P: Conn, DB9, Male, 1x1, 6A, Board Lock, RA, TH; EN: 201-2-00113; KEY Number: 201-2-00113@1; Mfg: TE CONNECTIVITY; Mfg Part No: 5747840-4
Q38 = TRANS_PMOS-ENX1_3P_C: Transistor, P-MOSFET, 20V, 2.5A, Vgs=12V, 0.5W, 0402; EN: 107-2-00200; KEY Number: 107-2-00200@1; Mfg: TEXAS INSTRUMENTS; Mfg Part No: CSD25481F4*; Temperature: -55°C to +150°C
R126 R254 R348 R570 R734 = RES: Res, Chip, 100K, 1/16W, 1%, 0402; EN: 101-1-00485; KEY Number: 101-1-00485@3; Mfg: WALSIN TECHNOLOGY CORP.; Mfg Part No: WR04X1003FTL; Temperature: -55°C to +155°C
U23 = IC_TSC2046_TSSOP-16P_A1: IC, TSC2046, Touch Screen Controller, TSSOP-16; EN: 301-0-02528; KEY Number: 301-0-02528@1; Mfg: TEXAS INSTRUMENTS; Mfg Part No: TSC2046IPWR; Temperature: -40°C to +85°C
U25 = IC_CAN-XCVR_8P_EP_A2: IC, MCP2562, High Speed CAN Transceiver, DFN-8; EN: 301-0-01166; KEY Number: 301-0-01166@1; Mfg: MICROCHIP; Temperature: -40°C to +125°C
U31 = IC_LIGHT-SENSOR_6P_EP_B_A1: Ambient Light Sensor, I2C, USON-6; EN: 304-1-00133; KEY Number: 304-1-00133@1; Mfg: TEXAS INSTRUMENTS; Mfg Part No: OPT3001DNP*; Temperature: -40°C to +85°C
U33 = IC_GATE_BUFX1_5P: IC, 74LVC1G07, Single Buffer/Driver, Open Drain O/P, SOT23-5; EN: 301-0-00088; KEY Number: 301-0-00088@1; Mfg: TEXAS INSTRUMENTS; Temperature: -40°C to +125°C
C299 = CAP_POL: Cap, Tant, 100uF, 10V, 20%, SizeB; EN: 102-2-00272; KEY Number: 102-2-00272@1; Mfg: AVX CORPORATION; Mfg Part No: TAJB107M010RNJ
C578 C579 = CAP_NP: Cap, Cer-X7R, 1uF, 16V, 10%, 0402; EN: 102-1-02367; KEY Number: 102-1-02367@1; Mfg: CAPAX TECHNOLOGIES INC.; Mfg Part No: 0402X105K160SNW; Temperature: -55°C to +125°C
DA1 = DIODE_NETX2_LED-GR_4P: LED, Single, (Green/Red), SMD0603; EN: 106-4-00053; KEY Number: 106-4-00053@1; Mfg: AVAGO TECHNOLOGIES; Temperature: -40°C to +85°C
FL1 FL2 = FIL_COM-MODE_4P_C_POL: Filter, Choke coil, CM, 90E, 330mA, Signal Line, SMD; EN: 303-0-00024; KEY Number: 303-0-00024@1; Mfg: MURATA MANUFACTURING CO,LTD; Temperature: -40°C to +85°C
J25 = CONN_USB-5X1_7P: Conn, USB Micro AB Receptacle, 1x1, RA, SMD; EN: 201-2-00027; KEY Number: 201-2-00027@1; Mfg: FCI; Mfg Part No: 10104111-0001LF
J26 = CONN_USBA-4X1_8P: Conn, USB 2.0, Type-A, Receptacle, 1x1, Shielded, RA, TH; EN: 201-2-01378; KEY Number: 201-2-01378@1; Mfg: TE CONNECTIVITY; Mfg Part No: 1-1734775-1; Temperature: 0°C to +50°C
R249 = RES: Res, Chip, 47K, 1/16W, 1%, 0402; EN: 101-1-03402; KEY Number: 101-1-03402@3; Mfg: SAMSUNG ELECTRO-MECHANICS AMERICA, INC; Mfg Part No: RC1005F473CS; Temperature: -55°C to +155°C
SW5-SW8 = SWITCH_PUSH_4P: Switch, Tactile, SPST-NO, 12V, 50mA, Vertical, SMD; EN: 205-1-00113; KEY Number: 205-1-00113@1; Mfg: E-SWITCH; Temperature: -20°C to +70°C
U30 = IC_LM3526-L_SOIC-8P: IC, LM3526, Dual USB Power Switch, SOIC-8; EN: 301-0-00254; KEY Number: 301-0-00254@1; Mfg: TEXAS INSTRUMENTS
C393 = CAP_NP: Cap, Cer-X7R, 0.033uF, 10V, 10%, 0402; EN: 102-1-00007; KEY Number: 102-1-00007@1; Mfg: AVX CORPORATION; Mfg Part No: 0402ZC333KAT2A; Temperature: -55°C to +125°C
C401 = CAP_NP: Cap, Cer-X5R, 2.2uF, 6.3V, 20%, 0402; EN: 102-1-01843; KEY Number: 102-1-01843@2; Mfg: WALSIN TECHNOLOGY CORP.; Mfg Part No: 0402X225M6R3C*; Temperature: -55°C to +85°C
J20 = CONN_B2B_2X15_34P_A: Conn, B2B, Receptacle, 2x15, 0.4mm, 5A, Shrouded, ST, SMD; EN: 201-1-00308; KEY Number: 201-1-00308@2; Mfg: PANASONIC; Mfg Part No: AXT530124; Temperature: -55°C to +85°C
U37 = IC_VOLT-MONITOR_6P: IC, TPS3808G25, Programmable-Delay Supervisory Circuit, SOT23-6; EN: 301-0-01221; KEY Number: 301-0-01221@1; Mfg: TEXAS INSTRUMENTS; Mfg Part No: TPS3808G25DBV; Temperature: -40°C to +125°C
U45 = IC_TXS0102_8P_A: IC, TXS0102, 2-Bit Bidirectional Voltage-Level Translator, VSSOP-8; EN: 301-0-00492; KEY Number: 301-0-00492@1; Mfg: TEXAS INSTRUMENTS; Mfg Part No: TXS0102DCUR; Temperature: -40°C to +85°C
Y4 = OSC_4P_R_A1: Osc, MEMS, 24MHz, +/-20ppm, 1.8V, LVCMOS, SMD; EN: 302-1-00182; KEY Number: 302-1-00182@1; Mfg: ABRACON CORPORATION; Mfg Part No: ASTMLPE-18-24.000MHZ-LJ-E; Temperature: -40°C to +85°C

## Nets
3V3OUT: C240.1 U18.6(3V3OUT)
AVCC_DBG_5V0: R157.2 U18.46(AVCC)
GND: C181.2 C182.2 C183.2 C184.2 C185.2 C186.2 C187.2 C188.2 C189.2 C190.2 C195.2 C196.2 C197.2 C216.2 C217.2 C218.2 C219.2 C220.2 C221.2 C222.2 C223.2 C224.2 C226.2 C227.2 C228.2 C239.2 C240.2 C241.2 C242.2 C243.1 C244.1 C245.2 C252.2 C261.2 C262.2 C263.2 C264.2 C265.2 C266.1 C279.2 C281.2 C282.2 C298.2 C299.2(CATHODE) C300.1 C301.2 C354.2 C361.2 C367.2 C368.2 C391.2 C392.2 C393.2 C401.2 C420.1 C421.1 C422.1 C423.1 C444.2 C445.2 C446.2 C447.2 C448.2 C456.2 C460.2 C461.2 C501.2 C505.2 C506.2 C510.2 C511.2 C525.2 C527.2 C528.2 C543.2 C544.2 C558.2 C570.2 C572.2 C573.2 C578.2 C579.2 D35.1(K) H2.3 H2.5 J10.2(GND1) J10.3(GND2) J11.5(GND) J14.9 J14.18 J14.27 J14.31 J14.33 J14.44 J19.5(GND) J19.6(DSR) J19.SH1 J19.SH2 J20.6 J20.11 J20.12 J20.14 J20.15 J20.18 J20.21 J20.24 J20.26 J20.29 J20.S1 J20.S2 J20.S3 J20.S4 J25.5(GND) J26.4(GND) J28.3(VSS1) J28.6(VSS2) J28.S1(GND1) J28.S2(GND2) J28.S3(GND3) J28.S4(GND4) L8.2 M1.1(GND1) M1.7(GND2) M1.9(GND3) M1.15(GND4) M1.16(GND5) M1.17(GND6) M1.19(GND7) M1.20(GND8) M1.23(GND9) M1.24(GND10) M1.28(GND11) M1.29(GND12) M1.30(GND13) M1.31(GND14) M1.33(GND15) M1.34(GND16) M1.35(GND17) M1.37(GND18) M1.39(GND19) M1.44(GND20) M1.45(GND21) M1.48(GND22) M1.49(GND23) M1.54(GND24) M1.55(GND25) M1.59(GND26) M1.61(GND27) M1.63(GND28) M1.64(GND29) M1.G1(GND30) M1.G2(GND31) M1.G3(GND32) M1.G4(GND33) M1.G5(GND34) M1.G6(GND35) M1.G7(GND36) M1.G8(GND37) M1.G9(GND38) M1.G10(GND39) M1.G11(GND40) M1.G12(GND41) M1.G13(GND42) M1.G14(GND43) M1.G15(GND44) M1.G16(GND45) M1.G17(GND46) M1.G18(GND47) M1.G19(GND48) M1.G20(GND49) M1.G21(GND50) M1.G22(GND51) M1.G23(GND52) M1.G24(GND53) M1.G25(GND54) M1.G26(GND55) M1.G27(GND56) M1.G28(GND57) M1.G29(GND58) M1.G30(GND59) M1.G31(GND60) M1.G32(GND61) M1.G33(GND62) M1.G34(GND63) M1.G35(GND64) M1.G36(GND65) P4.1 P5.1 P6.1 P7.1 P8.1 P10.1 P11.1 P13.1 P14.1 P17.1 P18.1 P19.1 P20.1 P21.1 P22.1 P23.1 P24.1 P25.1 P26.1 P27.1 Q7.2(SOURCE) Q8.2(EMITTER) Q25.2(SOURCE) R126.1 R163.2 R174.1 R250.2 R251.2 R254.1 R269.2 R294.1 R349.2 R567.2 R568.2 R683.2 R691.1 SW5.1 SW5.2 SW6.1 SW6.2 SW7.1 SW7.2 SW8.1 SW8.2 U10.A6(VSS1) U10.C4(VSSQ1) U10.E7(VSS2) U10.G5(VSS3) U10.H10(VSS4) U10.J5(VSS5) U10.K8(VSS6) U10.N2(VSSQ2) U10.N5(VSSQ3) U10.P4(VSSQ4) U10.P6(VSSQ5) U11.4(VSS) U11.9(VSS_EP) U17.4(GND) U18.9(GND1) U18.18(GND2) U18.25(GND3) U18.34(GND4) U18.45(AGND) U18.47(TEST) U19.4(GND) U23.6(GND) U25.2(VSS) U25.9(VSS_EP) U30.6(GND) U31.3(GND) U31.7(GND_EP) U33.3(GND) U37.2(GND) U45.2(GND) X5.2(GND1) X5.4(GND2) Y4.2(GND) Y5.2(GND) ; also on sheet 1 4 5 6 7 8 9 10 11 13 14 21
GND_USB_A: C301.1 J26.S1 J26.S2 J26.S3 J26.S4 R250.1
GND_USB_CONN: C242.1 J11.S1 J11.S2 J11.S3 J11.S4 J11.S5 J11.S6 R163.1
VCCI_eMMC: C510.1 C511.1 U10.C2(VDDIM)
VDD_1V8: C216.1 C461.1 C574.1 C575.1 FB35.1 FB36.2 FB39.2 M1.38(VIO_IN) Q39.1(GATE) R636.2 R638.1 R639.1 R640.2 R682.2 R707.2 R708.2 R709.2 R710.2 R711.2 U45.3(VCCA) ; also on sheet 1 5 6 7 8 10 13
VDD_3V3: C181.1 C182.1 C183.1 C189.1 C190.1 C194.1 C217.1 C218.1 C241.1 C245.1 C391.1 C460.1 C505.1 C543.1 C544.1 C574.2 C575.2 M1.46(VBAT_IN1) M1.47(VBAT_IN2) Q6.2(SOURCE) Q25.1(GATE) Q38.2(SOURCE) R92.1 R102.1 R104.1 R105.1 R168.2 R169.2 R170.2 R171.2 R224.2 R252.2 R253.2 R255.2 R257.2 R387.2 R637.2 R658.1 R674.1 R733.1 R734.1 R739.2 R740.2 U10.E6(VCC1) U10.F5(VCC2) U10.J10(VCC3) U10.K9(VCC4) U11.8(VCC) U17.8(VCC) U19.8(VCC) U25.5(VIO) U31.1(VDD) U45.7(VCCB) ; also on sheet 1 5 6 7 8 11 12 13 21
VDD_3V3_LCD: C263.1 C264.1 C265.1 C392.1 C558.1 J14.45 J14.46 Q38.3(DRAIN) R656.1 R733.2 U23.1(VCC+) U23.7(VBAT) U23.10(IOVDD) U33.5(VCC)
VDD_5V: C261.1 C262.1 C525.1 FB37.2 J14.47 J14.48 U30.7(IN) ; also on sheet 5 11
VDD_CAN: C279.1 C570.1 FB37.1 U25.3(VDD)
VDD_CLKGEN_1V8: C527.1 C528.1 FB39.1 R705.2 Y5.4(VDD)
VDD_CSI_2V8_1: C444.1 C445.1 FB31.2 J20.3
VDD_CSI_2V8_2: C354.1 C501.1 FB32.2 J20.5
VDD_CSI_XCLK: C448.1 FB35.2 R623.1 Y4.4(VDD)
VDD_LDO_2V8: FB31.1 FB32.1 ; also on sheet 1
VDD_SD: R99.1 R100.1 R101.1 R491.2 ; also on sheet 1 7
VDD_SD3: C184.1 C185.1 C186.1 C187.1 C188.1 R93.1 R94.1 U10.C6(VCCQ1) U10.M4(VCCQ2) U10.N4(VCCQ3) U10.P3(VCCQ4) U10.P5(VCCQ5) ; also on sheet 7
VDD_SD_CON: C195.1 C196.1 FB42.2 J28.4(VDD) R103.1 TP83.1
2G4_ANT: C529.2 M1.32(2G4_ANT1_WB)
32K_OSC_EN: R705.1 Y5.1(EN)
ADDR_LGHTSEN: R674.2 R683.1 U31.2(ADDR)
ALS_I2C_SCL: U31.4(SCL) ; also on sheet 12
ALS_I2C_SDA: U31.6(SDA) ; also on sheet 12
ALS_INT: R658.2 U31.5(INT) ; also on sheet 7
BT_DBG: M1.43(BT_UART_DBG) TP55.1
BT_REG_ON: M1.41(BT_EN) ; also on sheet 8
CAMERA_I2C_SCL: J20.7 R639.2 U45.4(A2)
CAMERA_I2C_SDA: J20.8 R638.2 U45.5(A1)
CAMERA_PWDN: J20.13 Q39.2(SOURCE) R636.1
CAN2_RX: U25.4(RXD) ; also on sheet 8
CAN2_TX: U25.1(TXD) ; also on sheet 8
CAN_STB: R224.1 U25.8(STBY) ; also on sheet 7
CANH: C282.1 J19.7(RTS) P14.2 R245.2 U25.7(CANH)
CANL: C281.1 J19.2(RXD) P13.2 R246.2 U25.6(CANL)
CAP_2G4_ANT: C529.1 C530.2 L8.1
CAP_IND_2G4_ANT: C530.1 J10.1(SIG)
CLK_32K: R706.1 Y5.3(OUT)
CSI_AGND: J20.2 J20.4 R269.1
CSI_I2C_SCL: U45.1(B2) ; also on sheet 12
CSI_I2C_SDA: U45.8(B1) ; also on sheet 12
CSI_PIN30: J20.30 R622.1
CSI_PWDN: Q39.3(DRAIN) R637.1 ; also on sheet 7
CSI_RESET: C456.1 J20.9 R630.1
CSI_VDD_1V8: C446.1 C447.1 FB36.1 J20.28 R622.2 R630.2
CSI_XCLK: J20.25 Y4.3(OUT)
CSI_XCLK_OE: R623.2 Y4.1(OE/ST#)
D_USB_DN: J11.2(D-) P19.2 R160.2
D_USB_DP: J11.3(D+) P18.2 R158.2
DBG_DA: R165.1 U18.2(EEDATA)
DBG_RXLED1: D8.2(A) R161.1
DBG_RXLED2: D10.2(A) R166.1
DBG_TXLED1: D9.2(A) R162.1
DBG_TXLED2: D11.2(A) R167.1
DBG_XTIN: C243.2 R164.1 U18.43(XTIN) X5.1
DBG_XTOUT: C244.2 R164.2 U18.44(XTOUT) X5.3
DEBUG_5V0: C226.1 C227.1 C228.1 C239.1 C361.1 FB10.2 R157.1 R161.2 R162.2 R165.2 R166.2 R167.2 R294.2 U18.3(VCC1) U18.4(RESET#) U18.14(VCCIOA) U18.31(VCCIOB) U18.42(VCC2)
DEBUG_5V0_USB: FB10.1 J11.1(VBUS) P17.2
ESPI3_MISO: R358.2 U23.12(DOUT) ; also on sheet 7
ESPI3_MOSI: R357.2 U23.14(DIN) ; also on sheet 7
ESPI3_SCLK: R356.2 U23.16(DCLK) ; also on sheet 7
FB_VDD_SD: FB42.1 Q6.3(DRAIN) R102.2
FT_RSTOUT_B: R159.2 U18.5(RSTOUT#)
FT_RX1: U17.3(2Y) U18.23(ADBUS1/RXD/D1/TDI/D0/AD1)
FT_RX2: U18.39(BDBUS1/RXD/D1/A9/FSCLK) U19.3(2Y)
FT_TX1: U17.2(1A) U18.24(ADBUS0/TXD/D0/TCK/SK/AD0)
FT_TX2: U18.40(BDBUS0/TXD/D0/A8/FSDI) U19.2(1A)
GWDOG_RST_B: C382.1 ; also on sheet 8
JT_PWR: C572.1 H2.1 R171.1
JTAG_GND1: H2.7 R567.1
JTAG_GND2: H2.9 R568.1
JTAG_MOD: R174.2 R387.1 ; also on sheet 7
JTAG_TCK: H2.4 ; also on sheet 7
JTAG_TDI: H2.8 R169.1 ; also on sheet 7
JTAG_TDO: H2.6 ; also on sheet 7
JTAG_TMS: H2.2 R170.1 ; also on sheet 7
JTAG_TRST_B: R172.1 ; also on sheet 7
LCD1_CLK: J14.32 ; also on sheet 7
LCD1_DATA0: J14.1 ; also on sheet 7
LCD1_DATA1: J14.2 ; also on sheet 7
LCD1_DATA2: J14.3 ; also on sheet 7
LCD1_DATA3: J14.4 ; also on sheet 7
LCD1_DATA4: J14.5 ; also on sheet 7 21
LCD1_DATA5: J14.6 ; also on sheet 7 21
LCD1_DATA6: J14.7 ; also on sheet 7 21
LCD1_DATA7: J14.8 ; also on sheet 7
LCD1_DATA8: J14.10 ; also on sheet 7
LCD1_DATA9: J14.11 ; also on sheet 7
LCD1_DATA10: J14.12 ; also on sheet 7 21
LCD1_DATA11: J14.13 ; also on sheet 7 21
LCD1_DATA12: J14.14 ; also on sheet 7 21
LCD1_DATA13: J14.15 ; also on sheet 7 21
LCD1_DATA14: J14.16 ; also on sheet 7 21
LCD1_DATA15: J14.17 ; also on sheet 7
LCD1_DATA16: J14.19 ; also on sheet 7
LCD1_DATA17: J14.20 ; also on sheet 7
LCD1_DATA18: J14.21 ; also on sheet 7
LCD1_DATA19: J14.22 ; also on sheet 7
LCD1_DATA20: J14.23 ; also on sheet 7
LCD1_DATA21: J14.24 ; also on sheet 7
LCD1_DATA22: J14.25 ; also on sheet 7
LCD1_DATA23: J14.26 ; also on sheet 7
LCD1_ENABLE: J14.28 ; also on sheet 7
LCD1_HSYNC: J14.29 ; also on sheet 7
LCD1_PWM: J14.50 R758.1 ; also on sheet 8
LCD1_RESET: J14.49 ; also on sheet 7
LCD1_TP_REF: C266.2 U23.9(VREF)
LCD1_VSYNC: J14.30 ; also on sheet 7
LCD_I2C_SCL: J14.42 ; also on sheet 12
LCD_I2C_SDA: J14.43 ; also on sheet 12
LCD_PWR_EN: Q38.1(GATE) R734.2 ; also on sheet 7
LED_BOOT_COMPL: DA1.3(GK) ; also on sheet 7
LED_BOOT_PROC: DA1.4(RK) ; also on sheet 7
LVLTXR_OE: R640.1 U45.6(OE)
MIPI_CSI_CLK_N: J20.20 ; also on sheet 8
MIPI_CSI_CLK_P: J20.19 ; also on sheet 8
MIPI_CSI_D0_N: J20.23 ; also on sheet 8
MIPI_CSI_D0_P: J20.22 ; also on sheet 8
MIPI_CSI_D1_N: J20.17 ; also on sheet 8
MIPI_CSI_D1_P: J20.16 ; also on sheet 8
MX7_ONOFF: C367.1 R249.1 SW6.3 SW6.4 ; also on sheet 7
MX7_RST_B: C368.1 D21.1(K) R347.1
OTG_VBUS: C298.1 FB18.2 Q24.3(DRAIN) R570.2 R571.1
OTG_VBUS_CTRL: Q24.1(GATE) Q25.3(DRAIN) R570.1
PMIC_ENABLE: R350.1 ; also on sheet 5 7
PMIC_ENABLE_ACDET: R736.1 ; also on sheet 5
POR_B: D26.2(A) ; also on sheet 5 7
QSPIA_DA0: U11.5(DQ0) ; also on sheet 7
QSPIA_DA1: U11.2(DQ1) ; also on sheet 7
QSPIA_DA2: U11.3(W#/DQ2) ; also on sheet 7
QSPIA_DA3: U11.7(HOLD#/DQ3) ; also on sheet 7
QSPIA_SCLK: U11.6(C) ; also on sheet 7
QSPIA_SS0_B: R92.2 U11.1(S#) ; also on sheet 7
RES_LCD1_PWM: D35.2(A) R758.2
RES_LED_BOOT_COMP: DA1.1(GA) R739.1
RES_LED_BOOT_PROC: DA1.2(RA) R740.1
RES_SD1_RST: Q8.1(BASE) R108.2
RES_VDD_SD_CON: Q7.3(DRAIN) R103.2
RX_LED1: D8.1(K) U18.12(ACBUS2/RXLED#/RD#/WR#/GPIOH2/IORDY)
RX_LED2: D10.1(K) U18.28(BCBUS2/RXLED#/RD#/WR#)
SCHO_MR_B: C382.2 D22.1(K) R349.1
SCHO_PWR_DISCH: D4.1(K) Q8.3(COLLECTOR) R107.2
SD1_CD_B: J28.10(CARD_DETECT_SWITCH) P26.2 R101.2 ; also on sheet 7
SD1_CLK: P24.2 R106.1 ; also on sheet 7
SD1_CLK_R: C197.1 J28.5(CLK) R106.2
SD1_CMD: J28.2(CMD) P25.2 R99.2 ; also on sheet 7
SD1_DATA0: J28.7(DAT0) P20.2 ; also on sheet 7
SD1_DATA1: J28.8(DAT1) P21.2 ; also on sheet 7
SD1_DATA2: J28.9(DAT2) P22.2 ; also on sheet 7
SD1_DATA3: J28.1(CD/DAT3) P23.2 ; also on sheet 7
SD1_RESET_B: R108.1 R491.1 ; also on sheet 7
SD1_WP: J28.11(WRITE_PROTECT_SWITCH) P27.2 R100.2 ; also on sheet 7
SD2_CLK: R176.1 ; also on sheet 7
SD2_CMD: R177.1 R711.1 ; also on sheet 7
SD2_DATA0: R178.1 R707.1 ; also on sheet 7
SD2_DATA1: R179.1 R708.1 ; also on sheet 7
SD2_DATA2: R180.1 R709.1 ; also on sheet 7
SD2_DATA3: R181.1 R710.1 ; also on sheet 7
SD3_CLK: R125.1 ; also on sheet 7
SD3_CLK_R: R125.2 U10.M6(CLK)
SD3_CMD: R94.2 U10.M5(CMD) ; also on sheet 7
SD3_DATA0: U10.A3(DAT0) ; also on sheet 7
SD3_DATA1: U10.A4(DAT1) ; also on sheet 7
SD3_DATA2: U10.A5(DAT2) ; also on sheet 7
SD3_DATA3: U10.B2(DAT3) ; also on sheet 7
SD3_DATA4: U10.B3(DAT4) ; also on sheet 7
SD3_DATA5: U10.B4(DAT5) ; also on sheet 7
SD3_DATA6: U10.B5(DAT6) ; also on sheet 7
SD3_DATA7: U10.B6(DAT7) ; also on sheet 7
SD3_RESET_B: R93.2 U10.K5(RST#) ; also on sheet 7
SD3_STROBE: R124.1 ; also on sheet 7
SD3_STROBE_R: R124.2 R691.2 U10.H5(DS)
SD_PWR_CTRL: C194.2 Q6.1(GATE) R105.2 R107.1
SD_PWR_DISCH: D4.2(A) Q7.1(GATE) R104.2
SPI3_MISO: J14.40 R358.1
SPI3_MOSI: J14.39 R357.1
SPI3_SCLK: J14.38 R356.1
SPI_SS_B: H4.3 J14.41
ST_CANH: C506.1 R245.1 R246.1
ST_CLK_32K: M1.36(EXT_32K) R706.2
ST_JTAG_TRS: D26.1(K) H2.10 R168.1 R172.2
SUPER_CT: C393.1 U37.4(CT)
SUPER_MR_B: D21.2(A) D22.2(A) R127.1 U37.3(MR#)
SUPER_RST_B: R350.2 R736.2 U37.1(RESET#)
SUPER_SENSE: C401.1 D16.2(A) R348.1 U37.5(SENSE)
SW_MX7_RST_B: R347.2 SW8.3 SW8.4
SW_USR_BT0: C578.1 R309.2 SW5.3 SW5.4
SW_USR_BT1: C579.1 R310.2 SW7.3 SW7.4
TOUCH_X1: J14.34 R590.2
TOUCH_X1_C: C420.2 R590.1 U23.2(X+)
TOUCH_X2: J14.35 R592.2
TOUCH_X2_C: C422.2 R592.1 U23.4(X-)
TOUCH_Y1: J14.36 R591.2
TOUCH_Y1_C: C421.2 R591.1 U23.3(Y+)
TOUCH_Y2: J14.37 R593.2
TOUCH_Y2_C: C423.2 R593.1 U23.5(Y-)
TP_BUSY: U23.13(BUSY) ; also on sheet 7
TP_ESPI3_SS2_B: U33.2(A) ; also on sheet 7
TP_ESPI_SS_B: H4.2 R656.2 U33.4(Y)
TP_INT_B: U23.11(PENIRQ#) ; also on sheet 7
TP_SPI_SS_B: H4.1 U23.15(CS#)
TX_LED1: D9.1(K) U18.11(ACBUS3/TXLED#/WR/RD#/GPIOH3/OSC/WR#)
TX_LED2: D11.1(K) U18.27(BCBUS3/TXLED#/WR/RD#/WR#)
UART1_RXD: U17.6(1Y) ; also on sheet 8
UART1_TXD: U17.5(2A) ; also on sheet 8
UART2_RXD: U19.6(1Y) ; also on sheet 8
UART2_TXD: U19.5(2A) ; also on sheet 8
UART6_CTS_B: R755.2 R756.2 TP53.1 ; also on sheet 8
UART6_RTS_B: R754.2 R757.2 TP52.1 ; also on sheet 8
UART6_RXD: M1.52(BT_HCI_TX_1V8) TP51.1 ; also on sheet 8
UART6_TXD: M1.53(BT_HCI_RX_1V8) TP50.1 ; also on sheet 8
USB_DN: R160.1 U18.8(USBDM)
USB_DP: R158.1 R159.1 U18.7(USBDP)
USB_HOST_N: FL2.3 J26.2(D-) P11.2
USB_HOST_P: FL2.2 J26.3(D+) P8.2
USB_HOST_VBUS: C299.1(ANODE) C300.2 J26.1(VBUS) P10.2 U30.5(OUTB) ; also on sheet 8
USB_OTG1_DN: FL1.3 ; also on sheet 8
USB_OTG1_DP: FL1.2 ; also on sheet 8
USB_OTG1_ID: J25.4(ID) P5.2 ; also on sheet 8
USB_OTG1_OC: R257.1 U30.2(FLAGA#) ; also on sheet 8
USB_OTG1_PWR: R126.2 R253.1 U30.1(ENA#) ; also on sheet 8
USB_OTG2_DN: FL2.4 ; also on sheet 8
USB_OTG2_DP: FL2.1 ; also on sheet 8
USB_OTG2_OC: R255.1 U30.3(FLAGB#) ; also on sheet 8
USB_OTG2_PWR: R252.1 R254.2 U30.4(ENB#) ; also on sheet 8
USB_OTG_N: FL1.4 J25.2(D-) P6.2
USB_OTG_P: FL1.1 J25.3(D+) P7.2
USB_OTG_PWR: FB18.1 J25.1(VBUS) P4.2
USB_OTG_SHIELD: C252.1 J25.S1 J25.S2 R251.1
USB_OTG_VBUS: Q24.2(SOURCE) R571.2 U30.8(OUTA) ; also on sheet 8
USB_SUSPEND1_B: U17.1(1OE) U17.7(2OE) U18.13(ACBUS1/SLEEP#/TXE#/RD#/GPIOH1/I/O1/A0)
USB_SUSPEND2_B: U18.29(BCBUS1/SLEEP#/TXE#/RD#/ALE/A0) U19.1(1OE) U19.7(2OE)
USR_BT0: R309.1 ; also on sheet 7
USR_BT1: R310.1 ; also on sheet 7
VSNVS: C573.1 D16.1(K) R127.2 R249.2 R348.2 U37.6(VDD) ; also on sheet 5 6
WL_DBG: M1.42(WL_UART_DBG) TP54.1
WL_IRQ: M1.14(WL_IRQ_1V8) R682.1 ; also on sheet 8
WL_REG_ON: M1.40(WLAN_EN) ; also on sheet 8
WL_RX: M1.26(GPIO2/WL_RS232_RX) TP56.1
WL_SDIO_CLK: C224.1 M1.8(WL_SDIO_CLK_1V8) R176.2
WL_SDIO_CMD: C223.1 M1.6(WL_SDIO_CMD_1V8) R177.2
WL_SDIO_D0: C222.1 M1.10(WL_SDIO_D0_1V8) R178.2
WL_SDIO_D1: C221.1 M1.11(WL_SDIO_D1_1V8) R179.2
WL_SDIO_D2: C220.1 M1.12(WL_SDIO_D2_1V8) R180.2
WL_SDIO_D3: C219.1 M1.13(WL_SDIO_D3_1V8) R181.2
WL_TX: M1.27(GPIO1/WL_RS232_TX) TP57.1
WL_UART6_CTS: M1.51(BT_HCI_CTS_1V8) R755.1 R757.1
WL_UART6_RTS: M1.50(BT_HCI_RTS_1V8) R754.1 R756.1

Not connected (* = marked no-connect by the designer): J11 4(ID)*; J14 M1* M2*; J19 1(DCD)* 3(TXD)* 4(DTR)* 8(CTS)* 9(RI)*; J20 1* 10* 27*; M1 2(GPIO11/RFU4)* 3(GPIO9/RFU2)* 4(GPIO10/RFU3)* 5(GPIO12/RFU5)* 18(NC1)* 21(NC2)* 22(NC3)* 25(GPIO4/RFU1)* 56(BT_AUD_IN)* 57(BT_AUD_OUT)* 58(BT_AUD_FSYNC)* 60(BT_AUD_CLK)* 62(NC4)*; U10 A1(NC1)* A2(NC2)* A7(RFU1)* A8(NC3)* A9(NC4)* A10(NC5)* A11(NC6)* A12(NC7)* A13(NC8)* A14(NC9)* B1(NC10)* B7(NC11)* B8(NC12)* B9(NC13)* B10(NC14)* B11(NC15)* B12(NC16)* B13(NC17)* B14(NC18)* C1(NC19)* C3(NC20)* C5(NC21)* C7(NC22)* C8(NC23)* C9(NC24)* C10(NC25)* C11(NC26)* C12(NC27)* C13(NC28)* C14(NC29)* D1(NC30)* D2(NC31)* D3(NC32)* D4(NC33)* D12(NC34)* D13(NC35)* D14(NC36)* E1(NC37)* E2(NC38)* E3(NC39)* E5(RFU2)* E8(RFU3)* E9(RFU4)* E10(RFU5)* E12(NC40)* E13(NC41)* E14(NC42)* F1(NC43)* F2(NC44)* F3(NC45)* F10(RFU6)* F12(NC46)* F13(NC47)* F14(NC48)* G1(NC49)* G2(NC50)* G3(NC51)* G10(RFU7)* G12(NC52)* G13(NC53)* G14(NC54)* H1(NC55)* H2(NC56)* H3(NC57)* H12(NC58)* H13(NC59)* H14(NC60)* J1(NC61)* J2(NC62)* J3(NC63)* J12(NC64)* J13(NC65)* J14(NC66)* K1(NC67)* K2(NC68)* K3(NC69)* K6(RFU8)* K7(RFU9)* K10(RFU10)* K12(NC70)* K13(NC71)* K14(NC72)* L1(NC73)* L2(NC74)* L3(NC75)* L12(NC76)* L13(NC77)* L14(NC78)* M1(NC79)* M2(NC80)* M3(NC81)* M7(NC82)* M8(NC83)* M9(NC84)* M10(NC85)* M11(NC86)* M12(NC87)* M13(NC88)* M14(NC89)* N1(NC90)* N3(NC91)* N6(NC92)* N7(NC93)* N8(NC94)* N9(NC95)* N10(NC96)* N11(NC97)* N12(NC98)* N13(NC99)* N14(NC100)* P1(NC101)* P2(NC102)* P7(NC103)* P8(NC104)* P9(NC105)* P10(RFU11)* P11(NC106)* P12(NC107)* P13(NC108)* P14(NC109)*; U18 1(EESK)* 10(SI/WUA)* 15(ACBUS0/TXDEN/RXF#/WR#/GPIOH0/I/O0/CS#)* 16(ADBUS7/RI#/D7/GPIOL3/AD7)* 17(ADBUS6/DCD#/D6/GPIOL2/AD6)* 19(ADBUS5/DSR#/D5/GPIOL1/AD5)* 20(ADBUS4/DTR#/D4/GPIOL0/AD4)* 21(ADBUS3/CTS#/D3/TMS/CS/AD3)* 22(ADBUS2/RTS#/D2/TDO/DI/AD2)* 26(SI/WUB)* 30(BCBUS0/TXDEN/RXF#/WR#/CS#)* 32(BDBUS7/RI#/D7/A15)* 33(BDBUS6/DCD#/D6/A14)* 35(BDBUS5/DSR#/D5/A13)* 36(BDBUS4/DTR#/D4/A12)* 37(BDBUS3/CTS#/D3/A11/FSCTS)* 38(BDBUS2/RTS#/D2/A10/FSDO)* 41(PWREN#)* 48(EECS)*; U23 8(AUX)*; U33 1(NC)*

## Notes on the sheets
sheet 15
- WiFi/BT
- TP54, TP55, TP56, TP57 are for debugg purpose
sheet 16
- Power Button
- User Button
- Status LED
- USB OTG
- USB HOST
- Layout: USB 90 ohm differential pairs
- Layout: USB 90 ohm differential pairs
- Keep ESD Diodes near USB connector
- USB Power
- Keep ESD Diodes near USB connector
sheet 17
- LCD
- ADAFRUIT LCD
- CAN
- I2C & SPI are NOT used
  on this LCD module.
  They are reserved here
  to support other
  modules.
- Keep ESD Diodes near CAN connector
- Ambient Light Sensor
- Place C265 near VBAT
- I2C Addr: 0x44
- 1.8V
- 3.3V
sheet 18
- eMMC 5.0
- QSPI NOR  FLASH
- Decoupling capacitor
  should connect close to
  power and ground
- SD CARD
- Note:Remove R103 if R102 is populated
- Stitching Capacitors
  for SD1 signals
- VCC_SD:47 uF capacitor according to
  Appendix E.1
  of the Physical Layer Specification of
  SD 3.01
- Keep ESD Diodes near SD connector
sheet 19
- CSI
- MIPI_CSI_D0_N
- MIPI_CSI_D0_P
- MIPI_CSI_CLK_N
- Differential Pairs
- MIPI_CSI_CLK_P
- MIPI_CSI_D1_N
- MIPI_CSI_D1_P
- TXSO102 Have internal pull up of value 10K at
  A1, A2, B1, B2 pins
- WATCH DOG
sheet 20
- DEBUG UART
- Note:
  Debug UART1 for Cortex-A7
  Debug UART2 for Cortex-M4
- Layout:Route 90 ohm
  differential for USB
- Layout note:
  Place R776, R777 close to
   the micro usb connector
- Keep ESD Diodes near USB connector
- Option: Discharge resistor for debug uart
- JTAG
